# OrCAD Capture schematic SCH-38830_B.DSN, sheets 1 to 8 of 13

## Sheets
1 08 SPDIF: size C; title: MIMXRT1015-EVK; rev: B; company: Freescale Semiconductor; note: SCH-38830, PDF: SPF-38830; note: 6501 William Cannon Drive West; note: Austin, TX 78735-8598
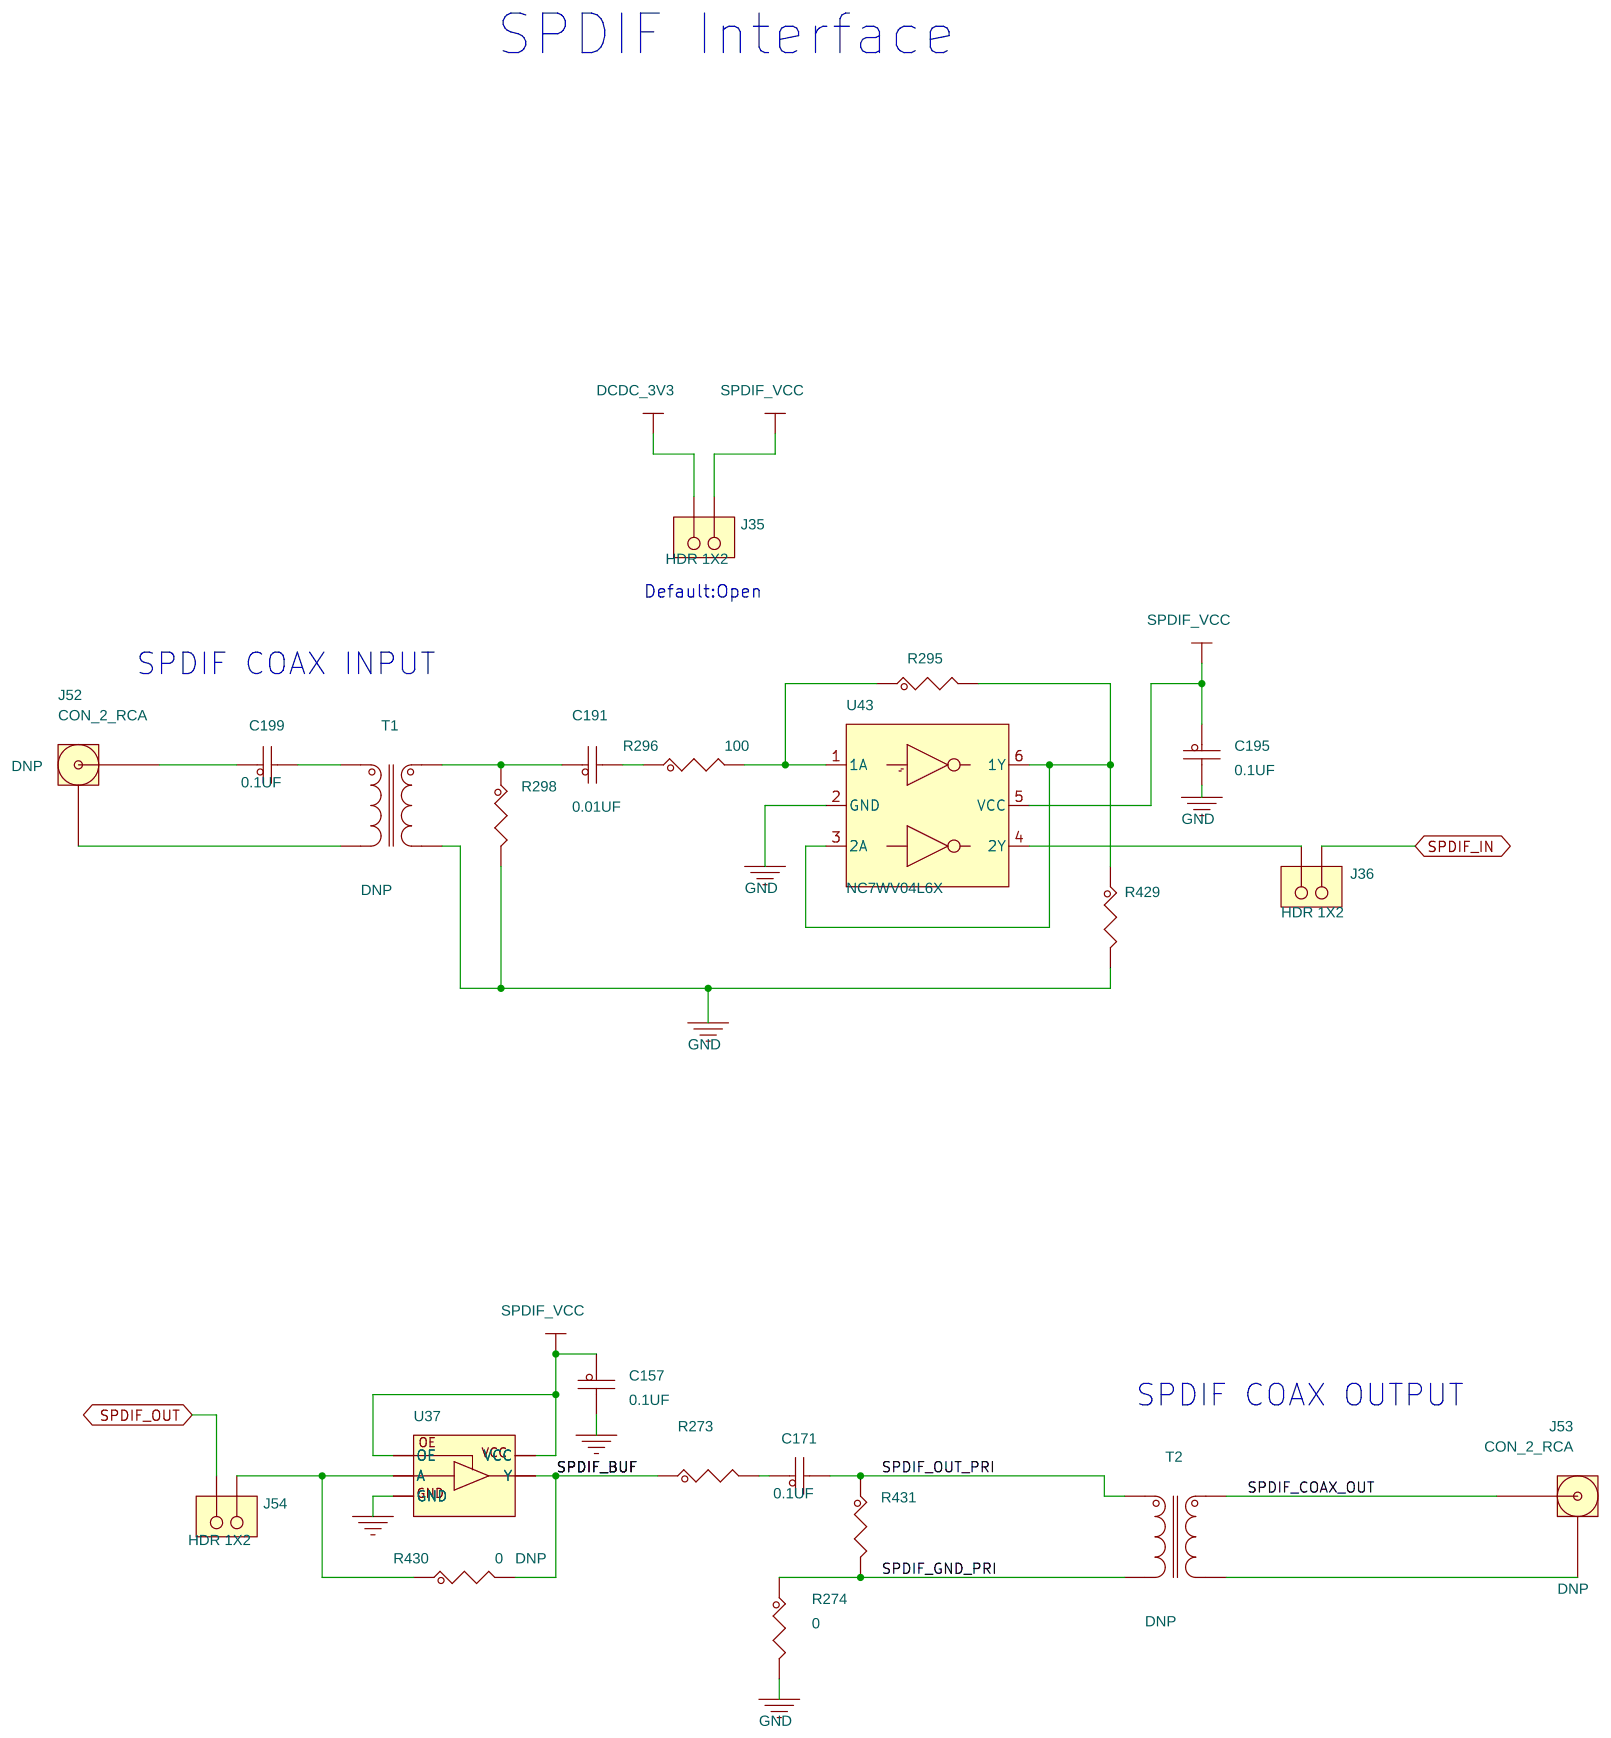
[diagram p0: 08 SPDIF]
2 01 COVER: company: NXP Semiconductors
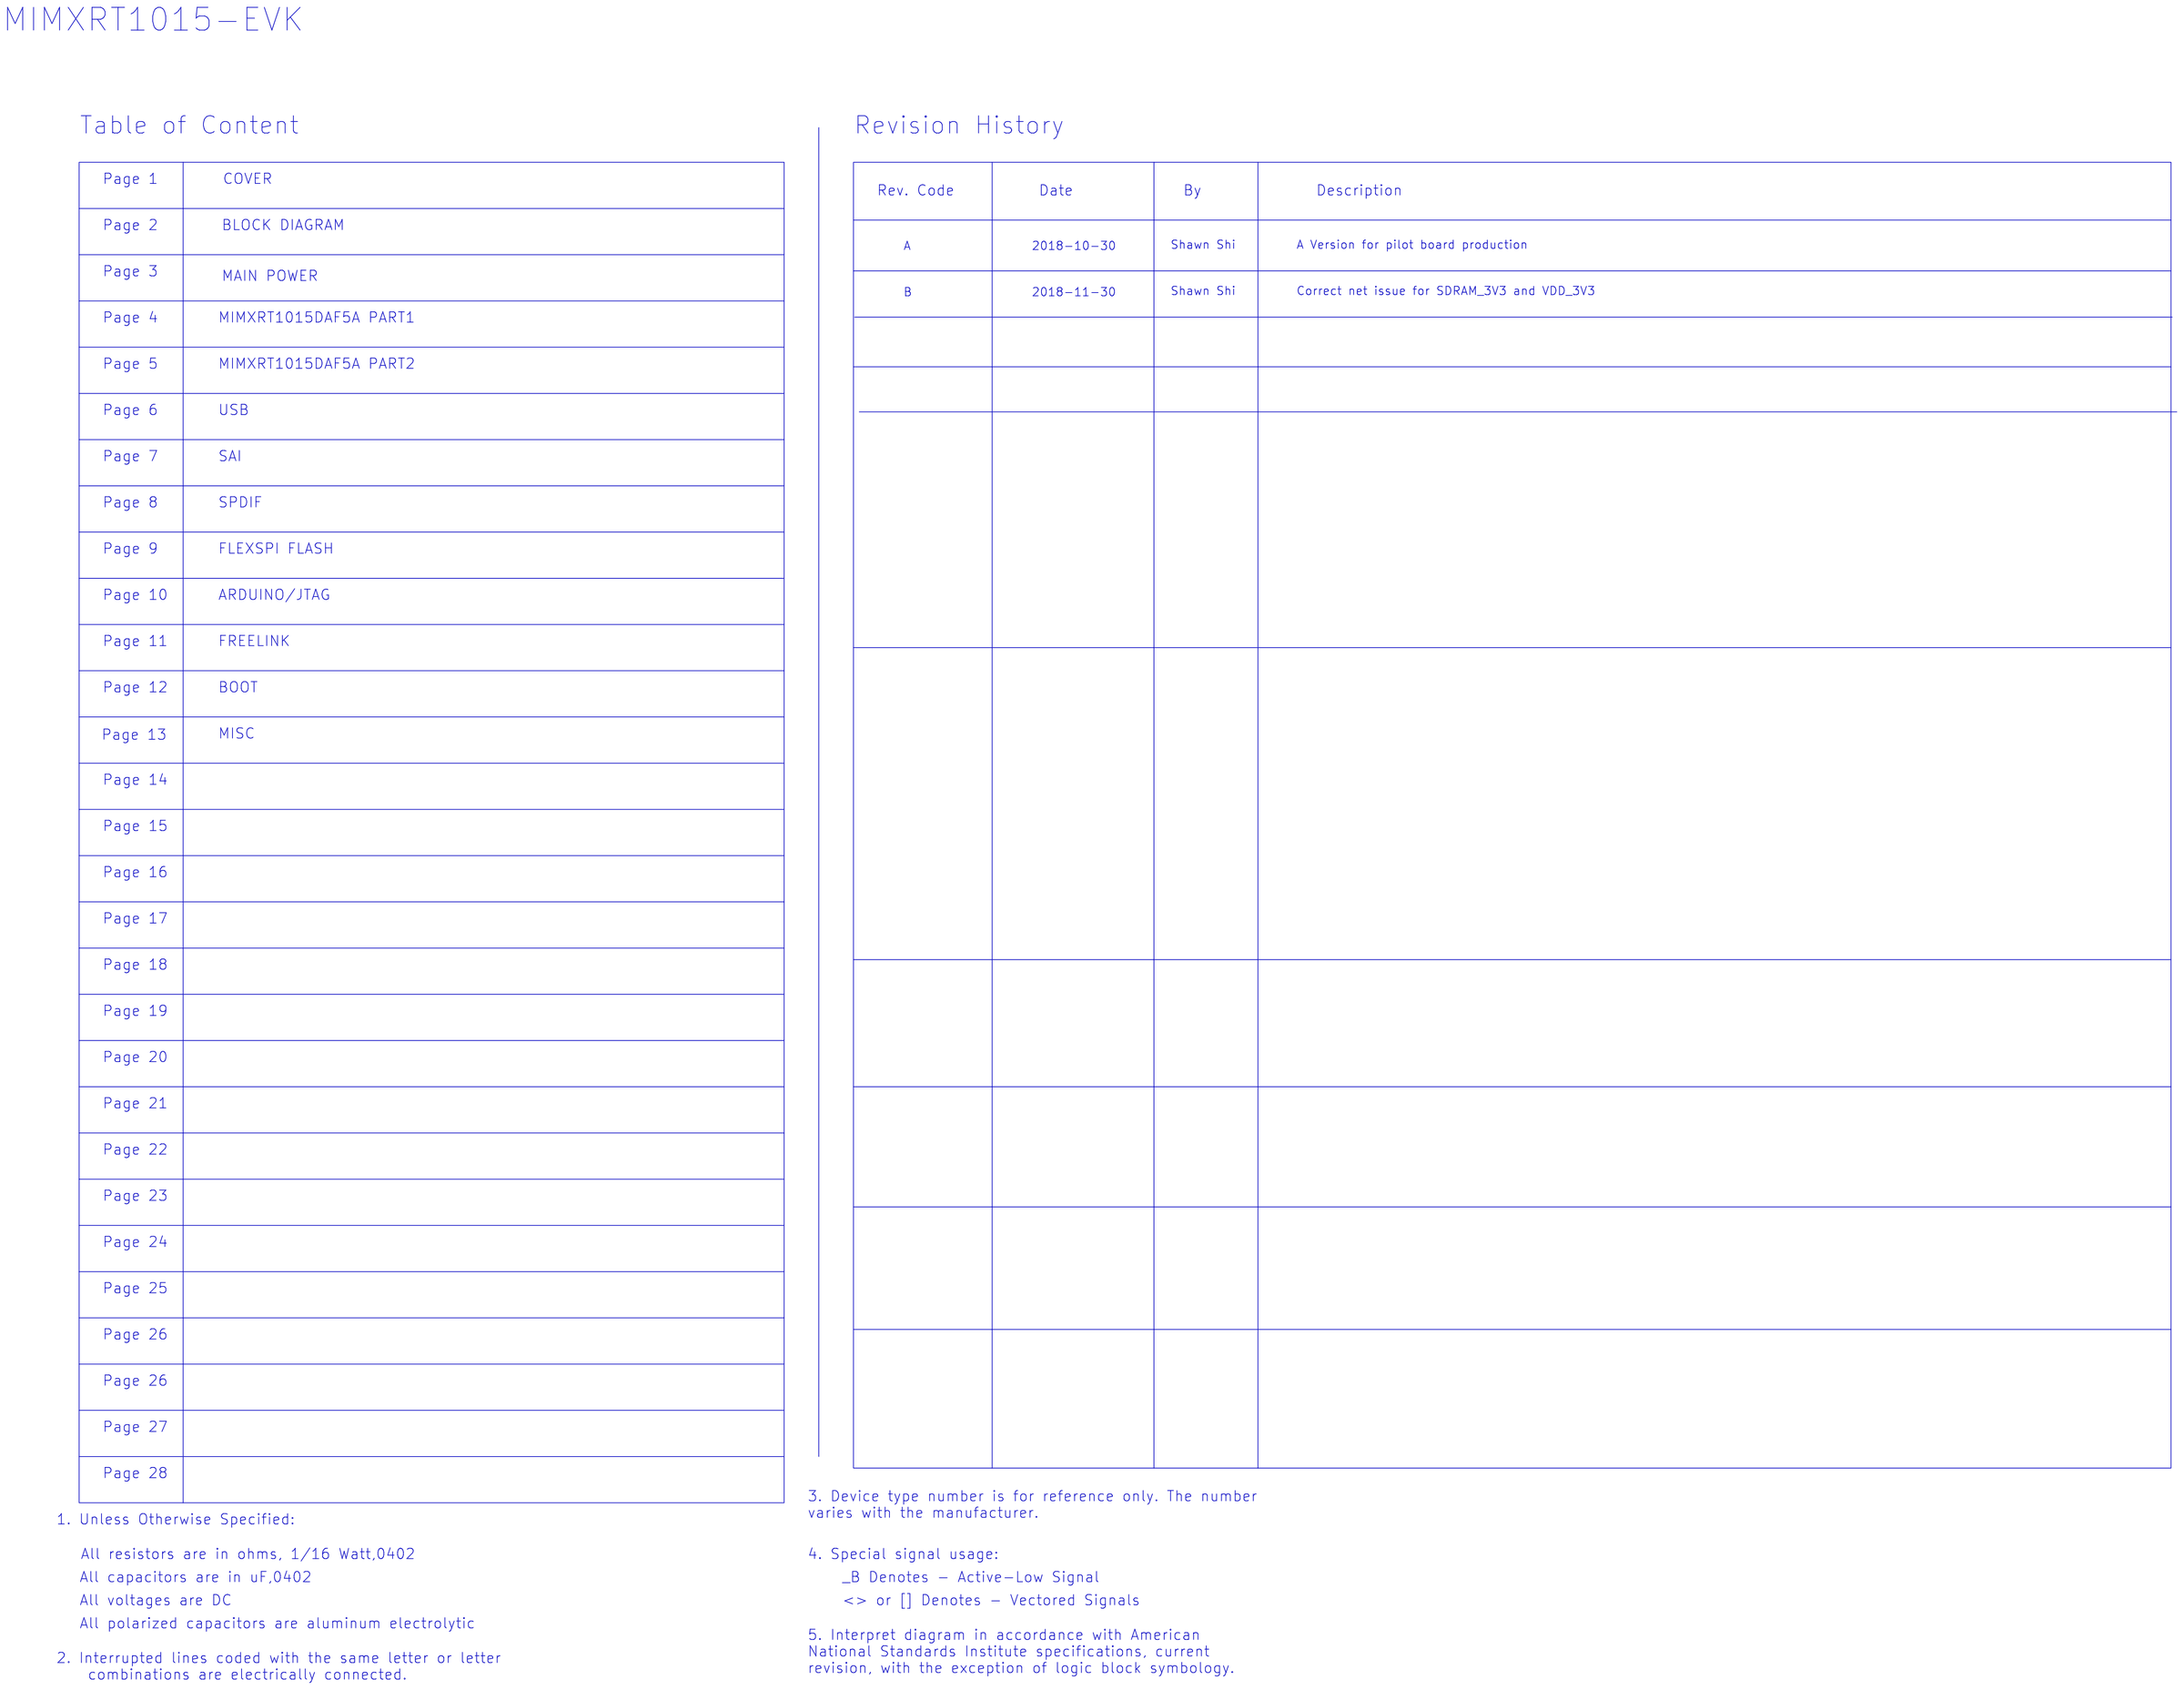
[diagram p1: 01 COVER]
3 02 BLOCK DIAGRAM
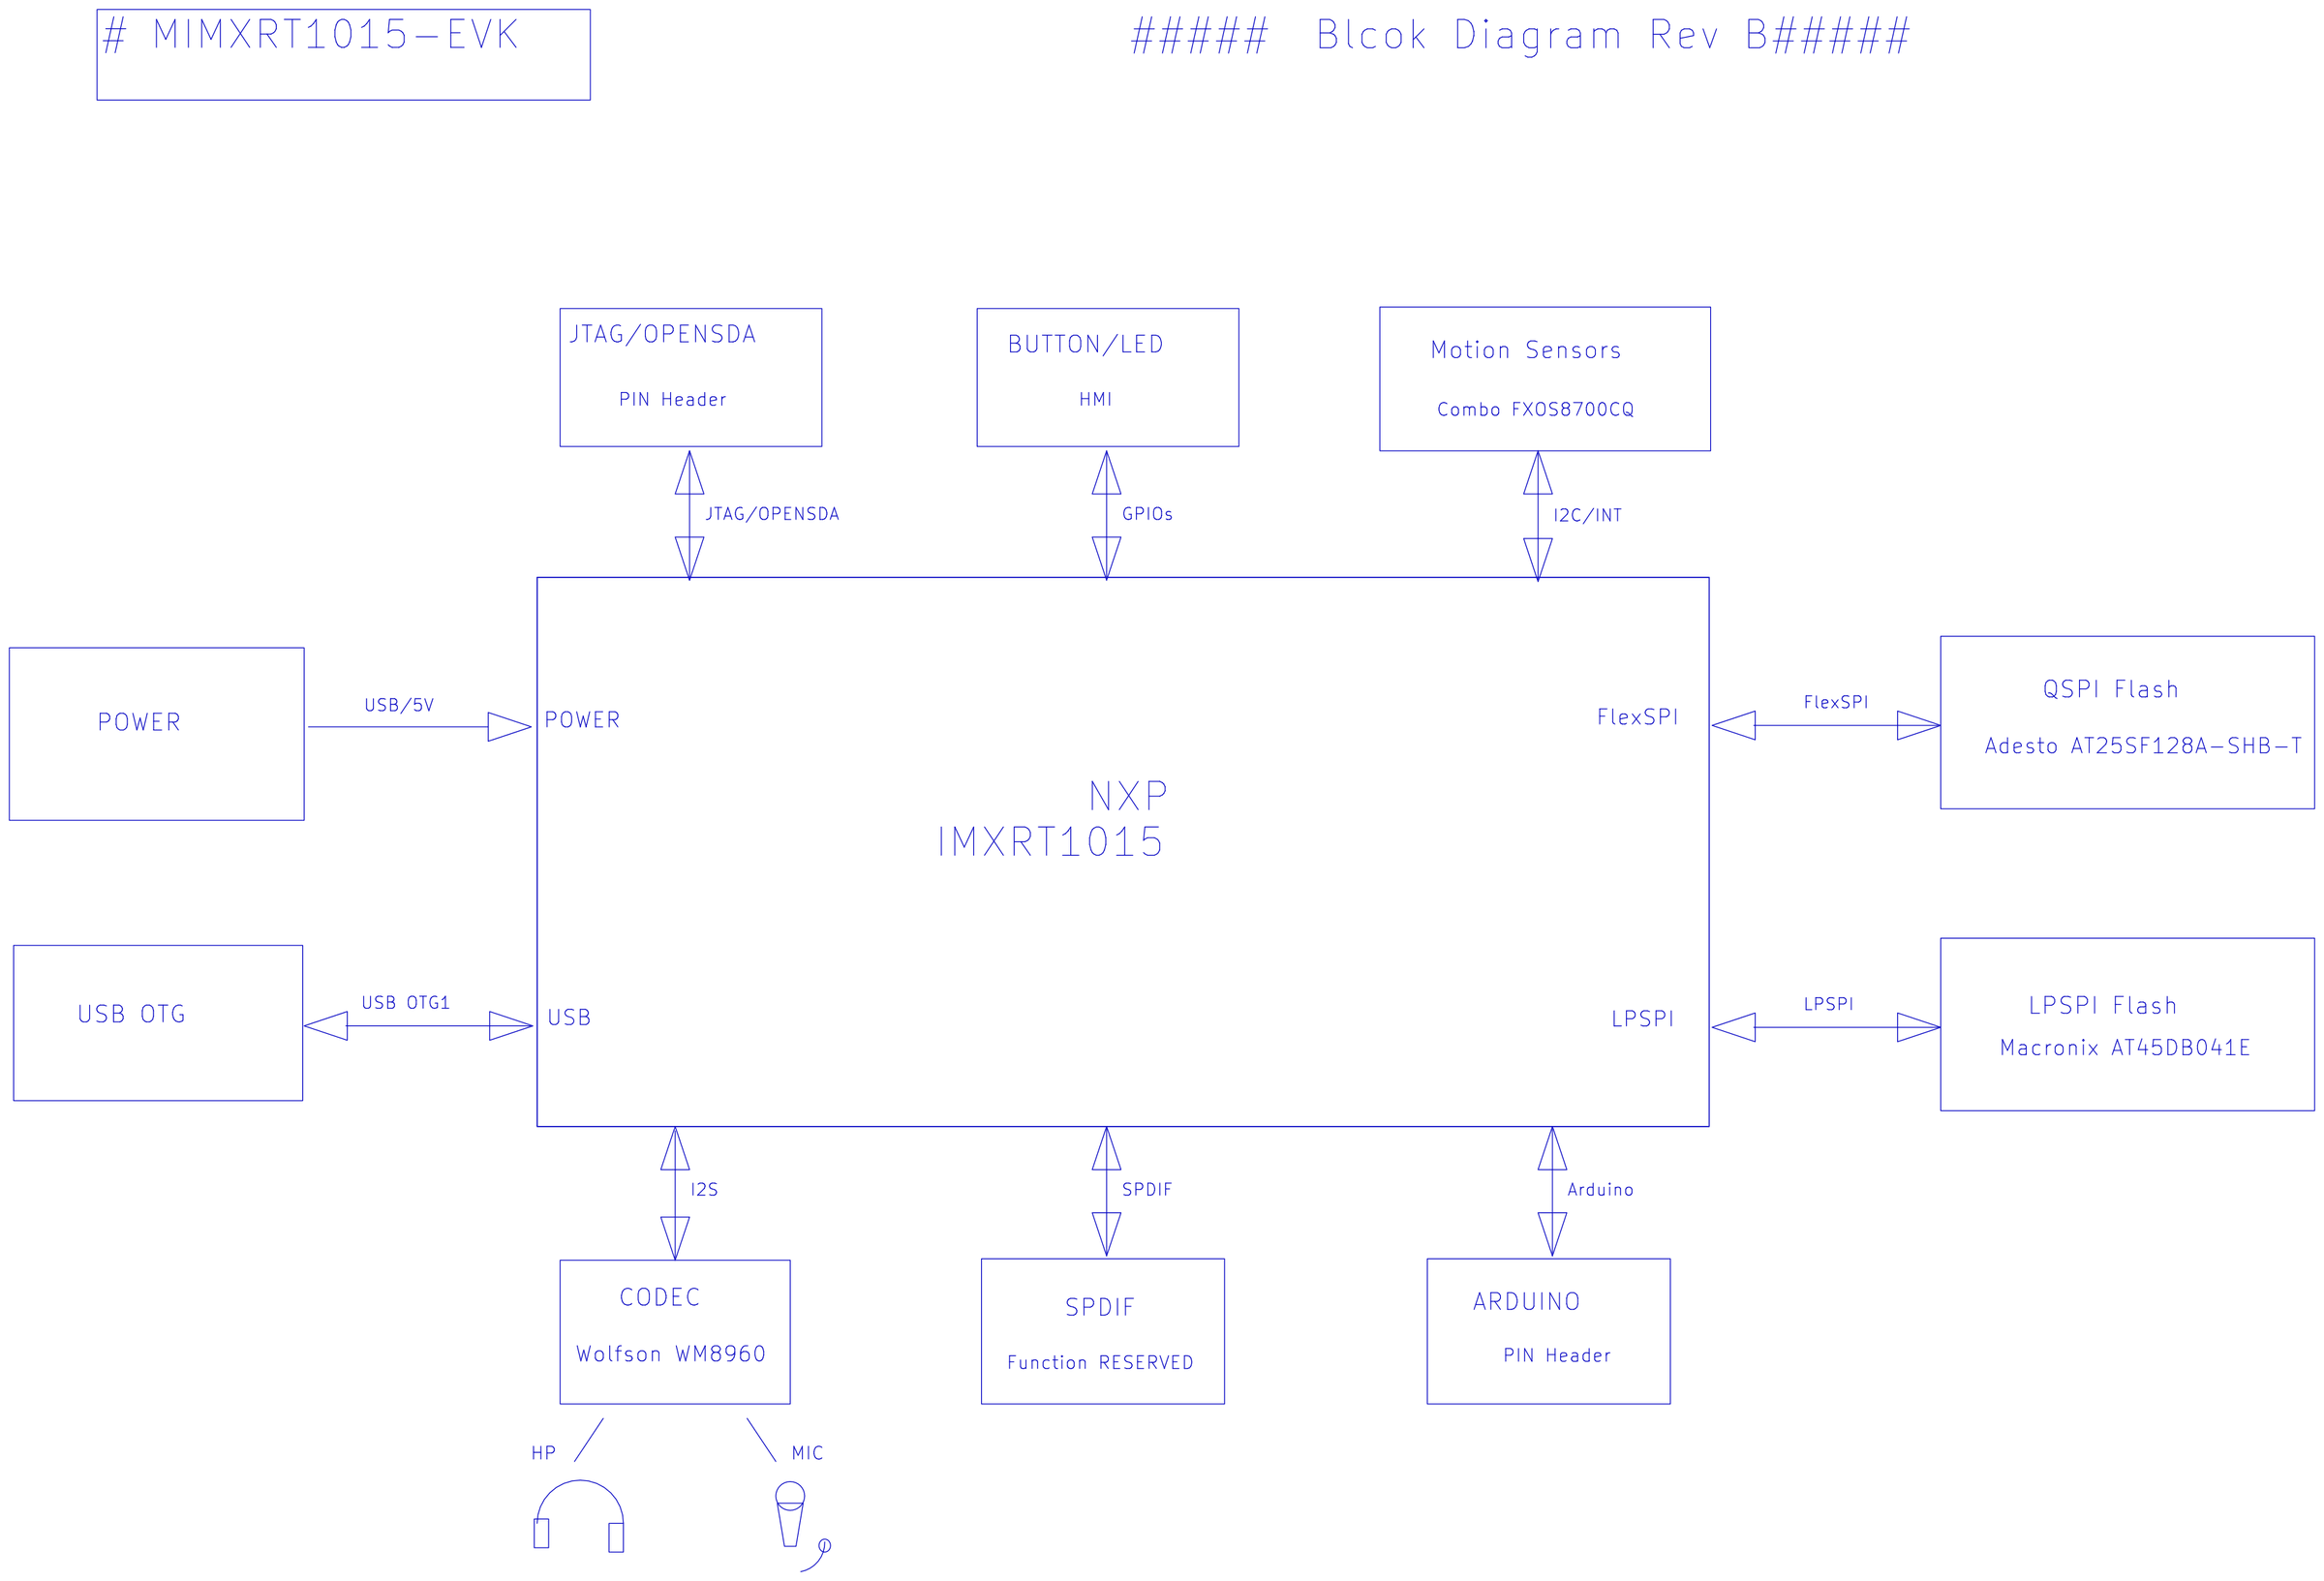
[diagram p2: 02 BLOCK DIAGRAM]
4 03 MAIN POWER: size C
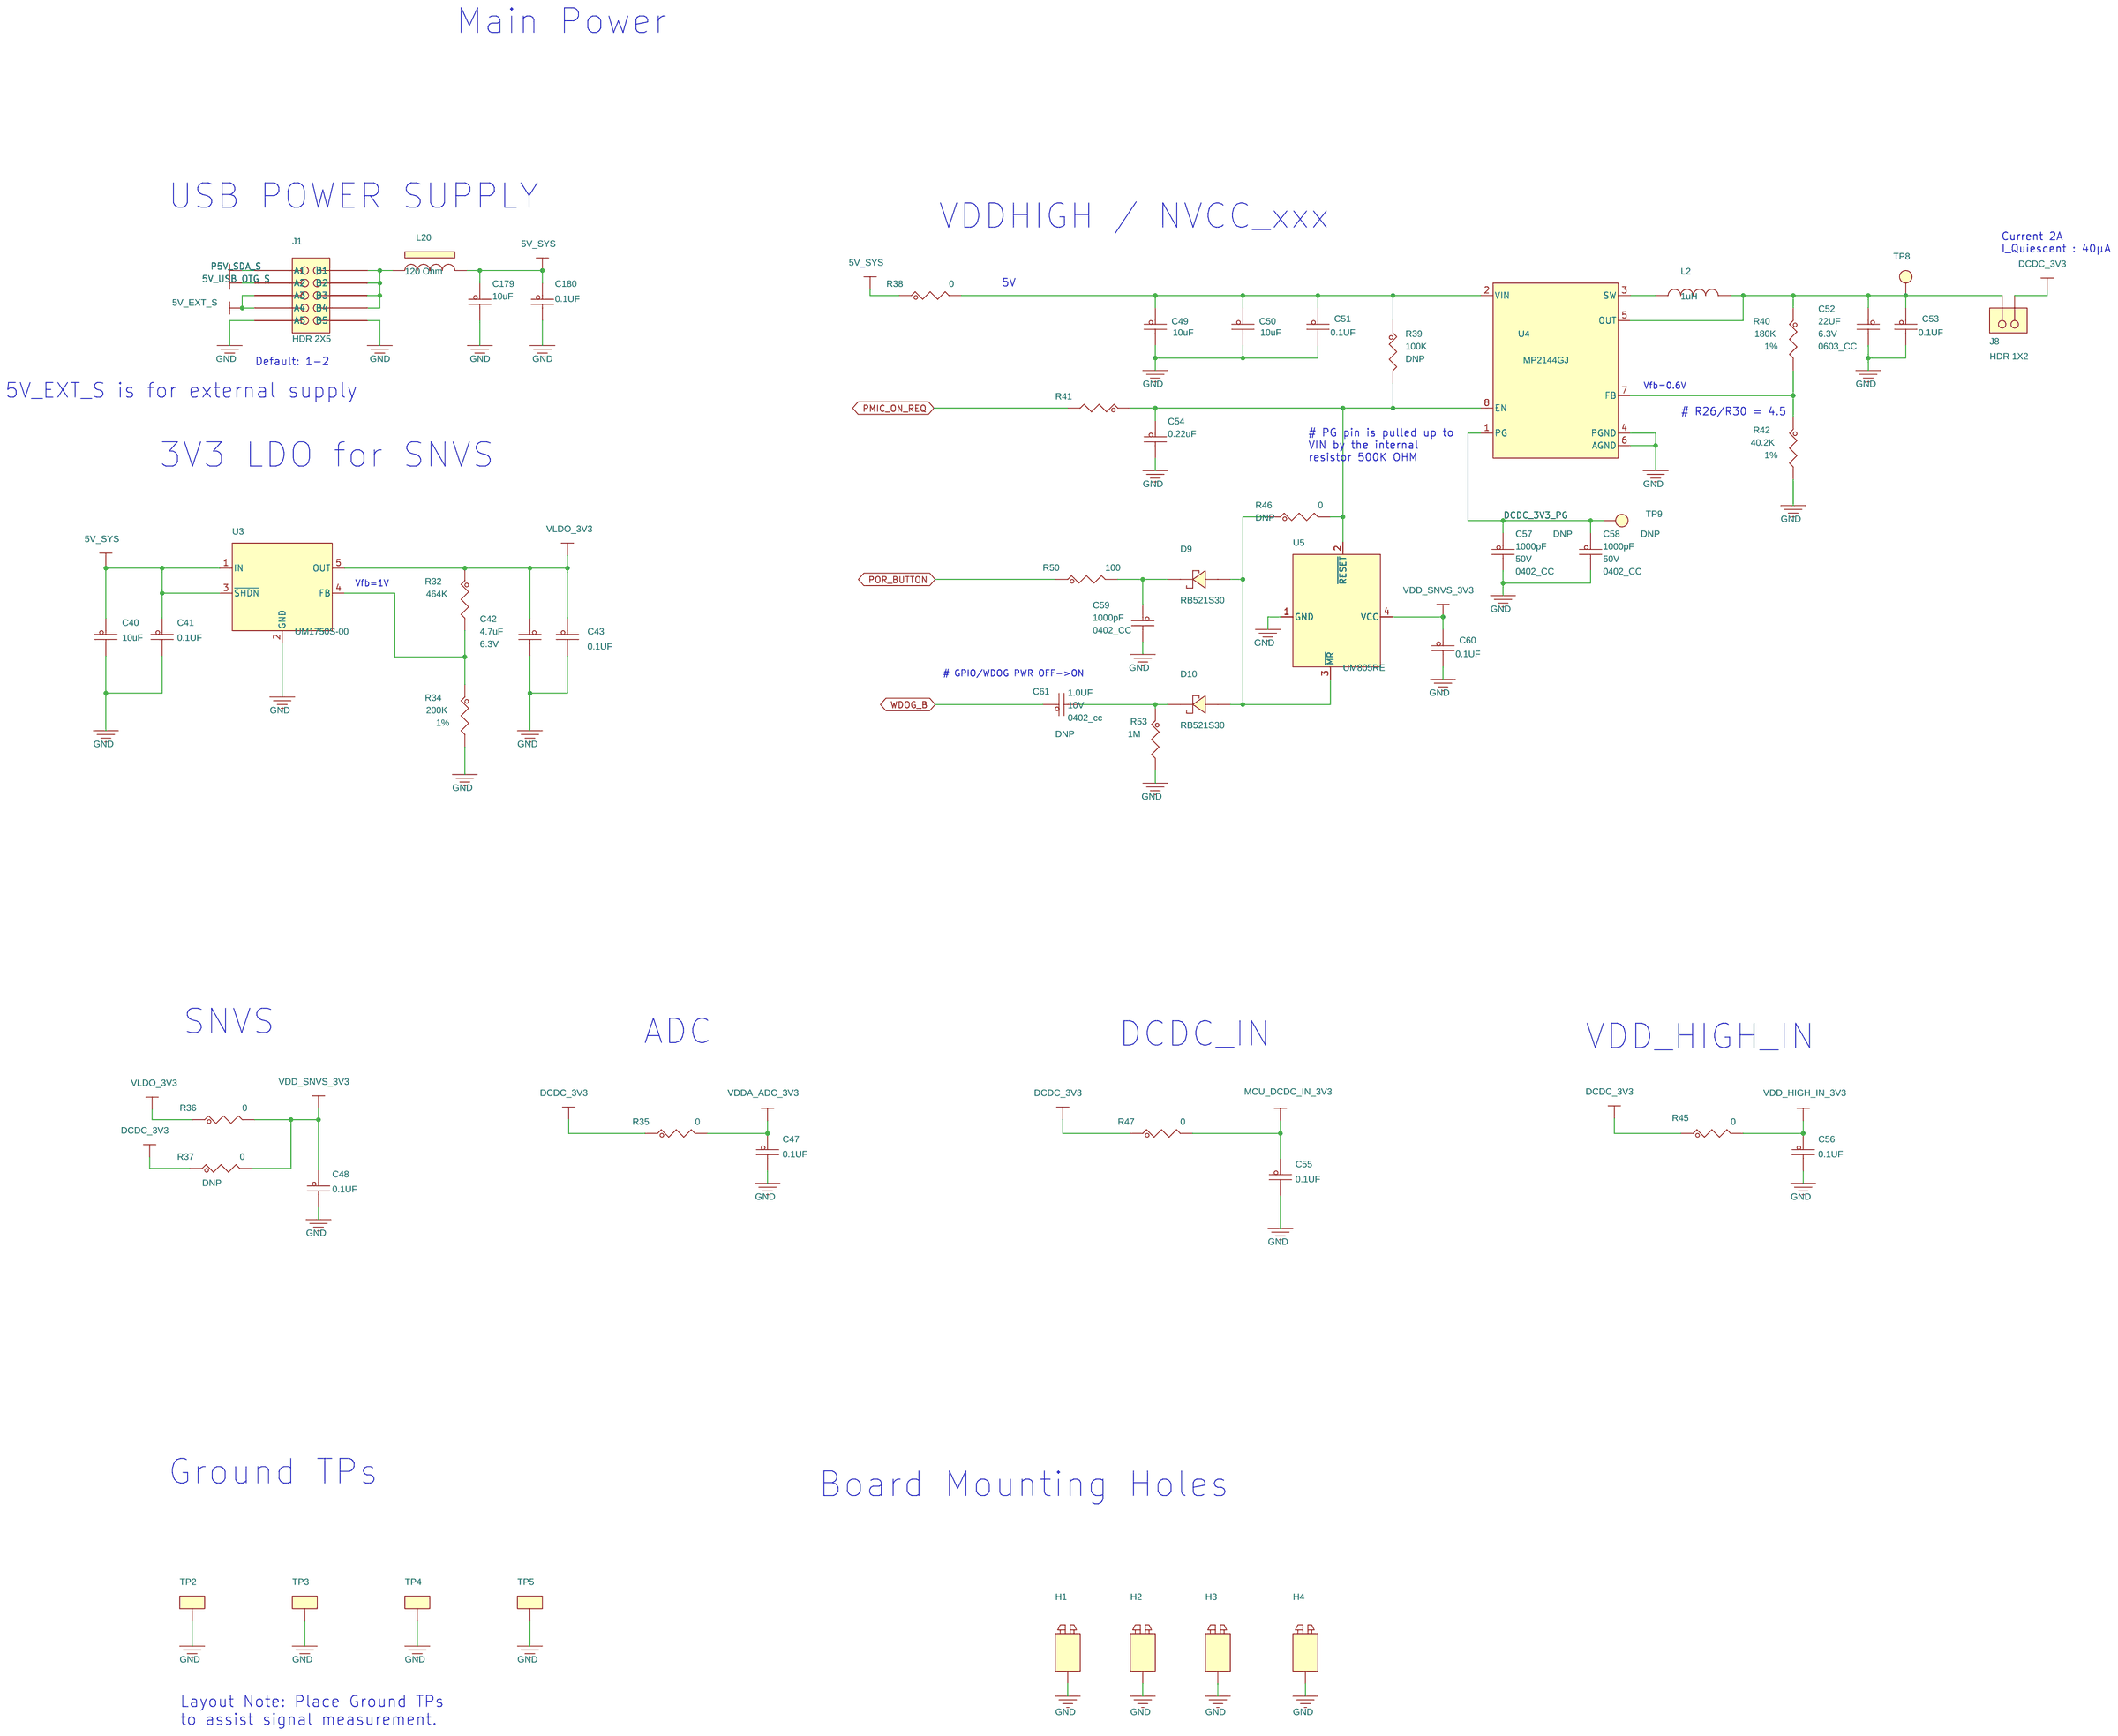
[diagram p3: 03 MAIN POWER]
5 04 MIMXRT1015DAF5A PART1: size C
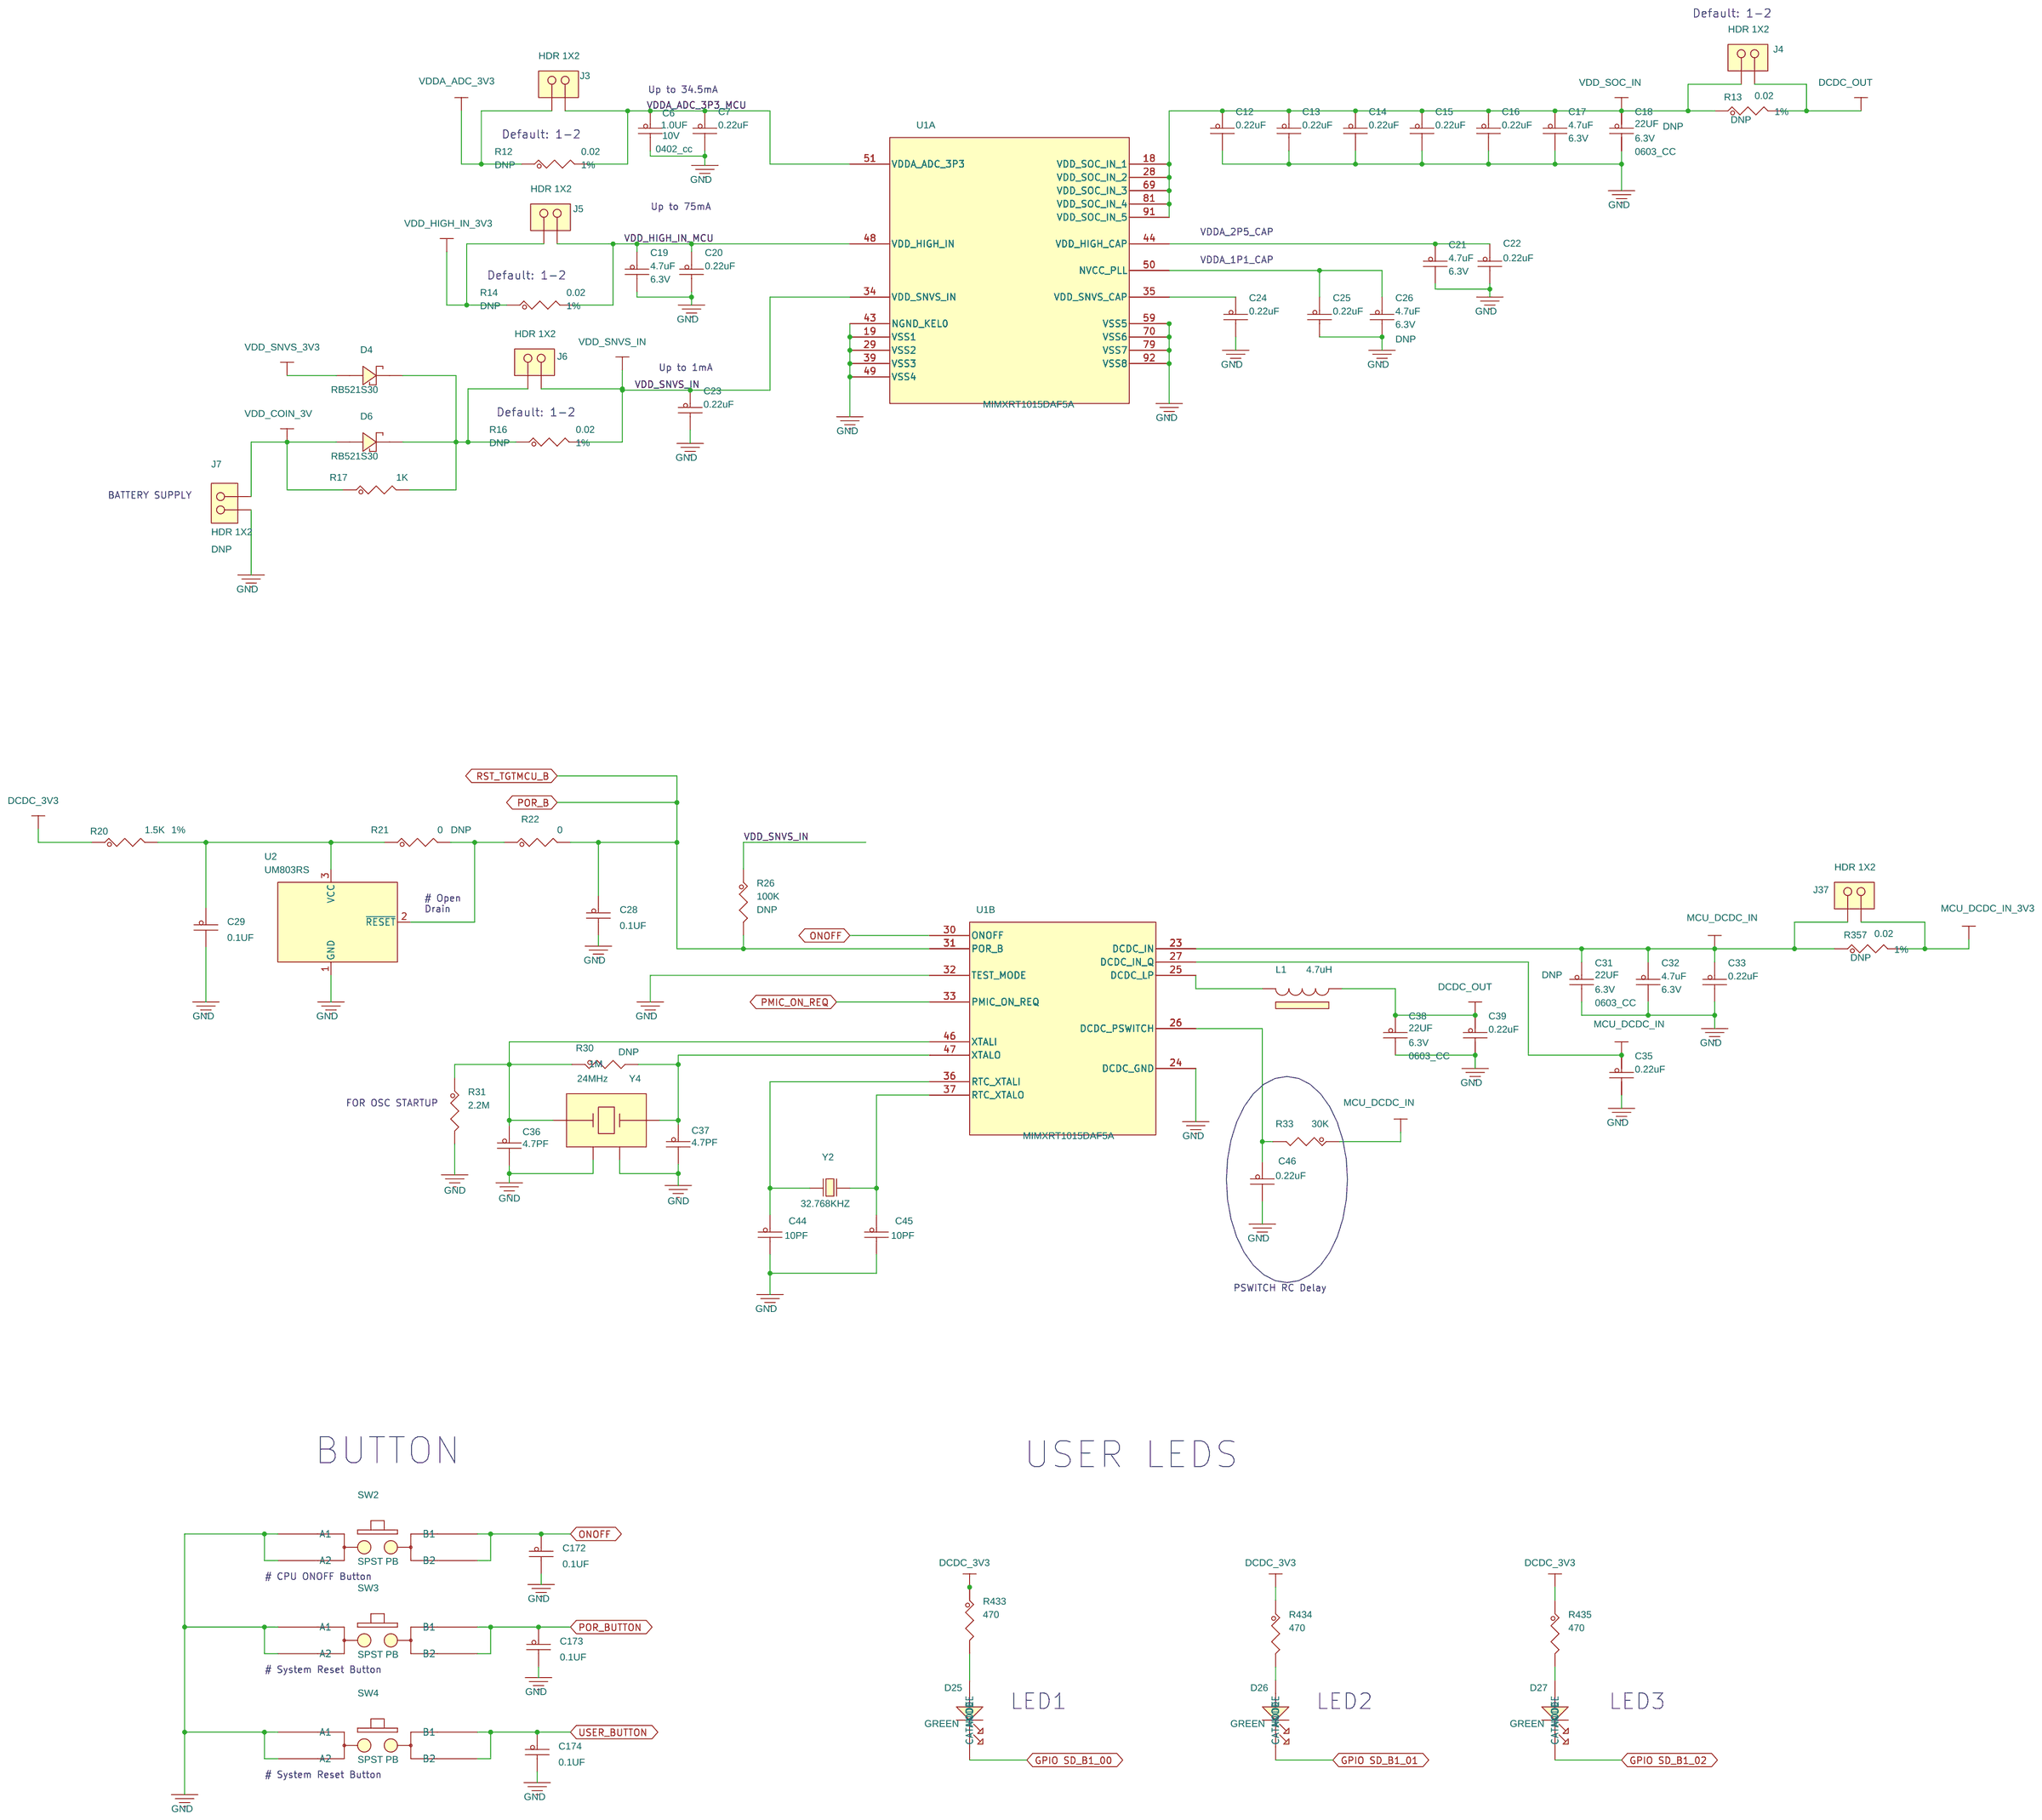
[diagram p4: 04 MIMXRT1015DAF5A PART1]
6 05 MIMXRT1015DAF5A PART2: size C
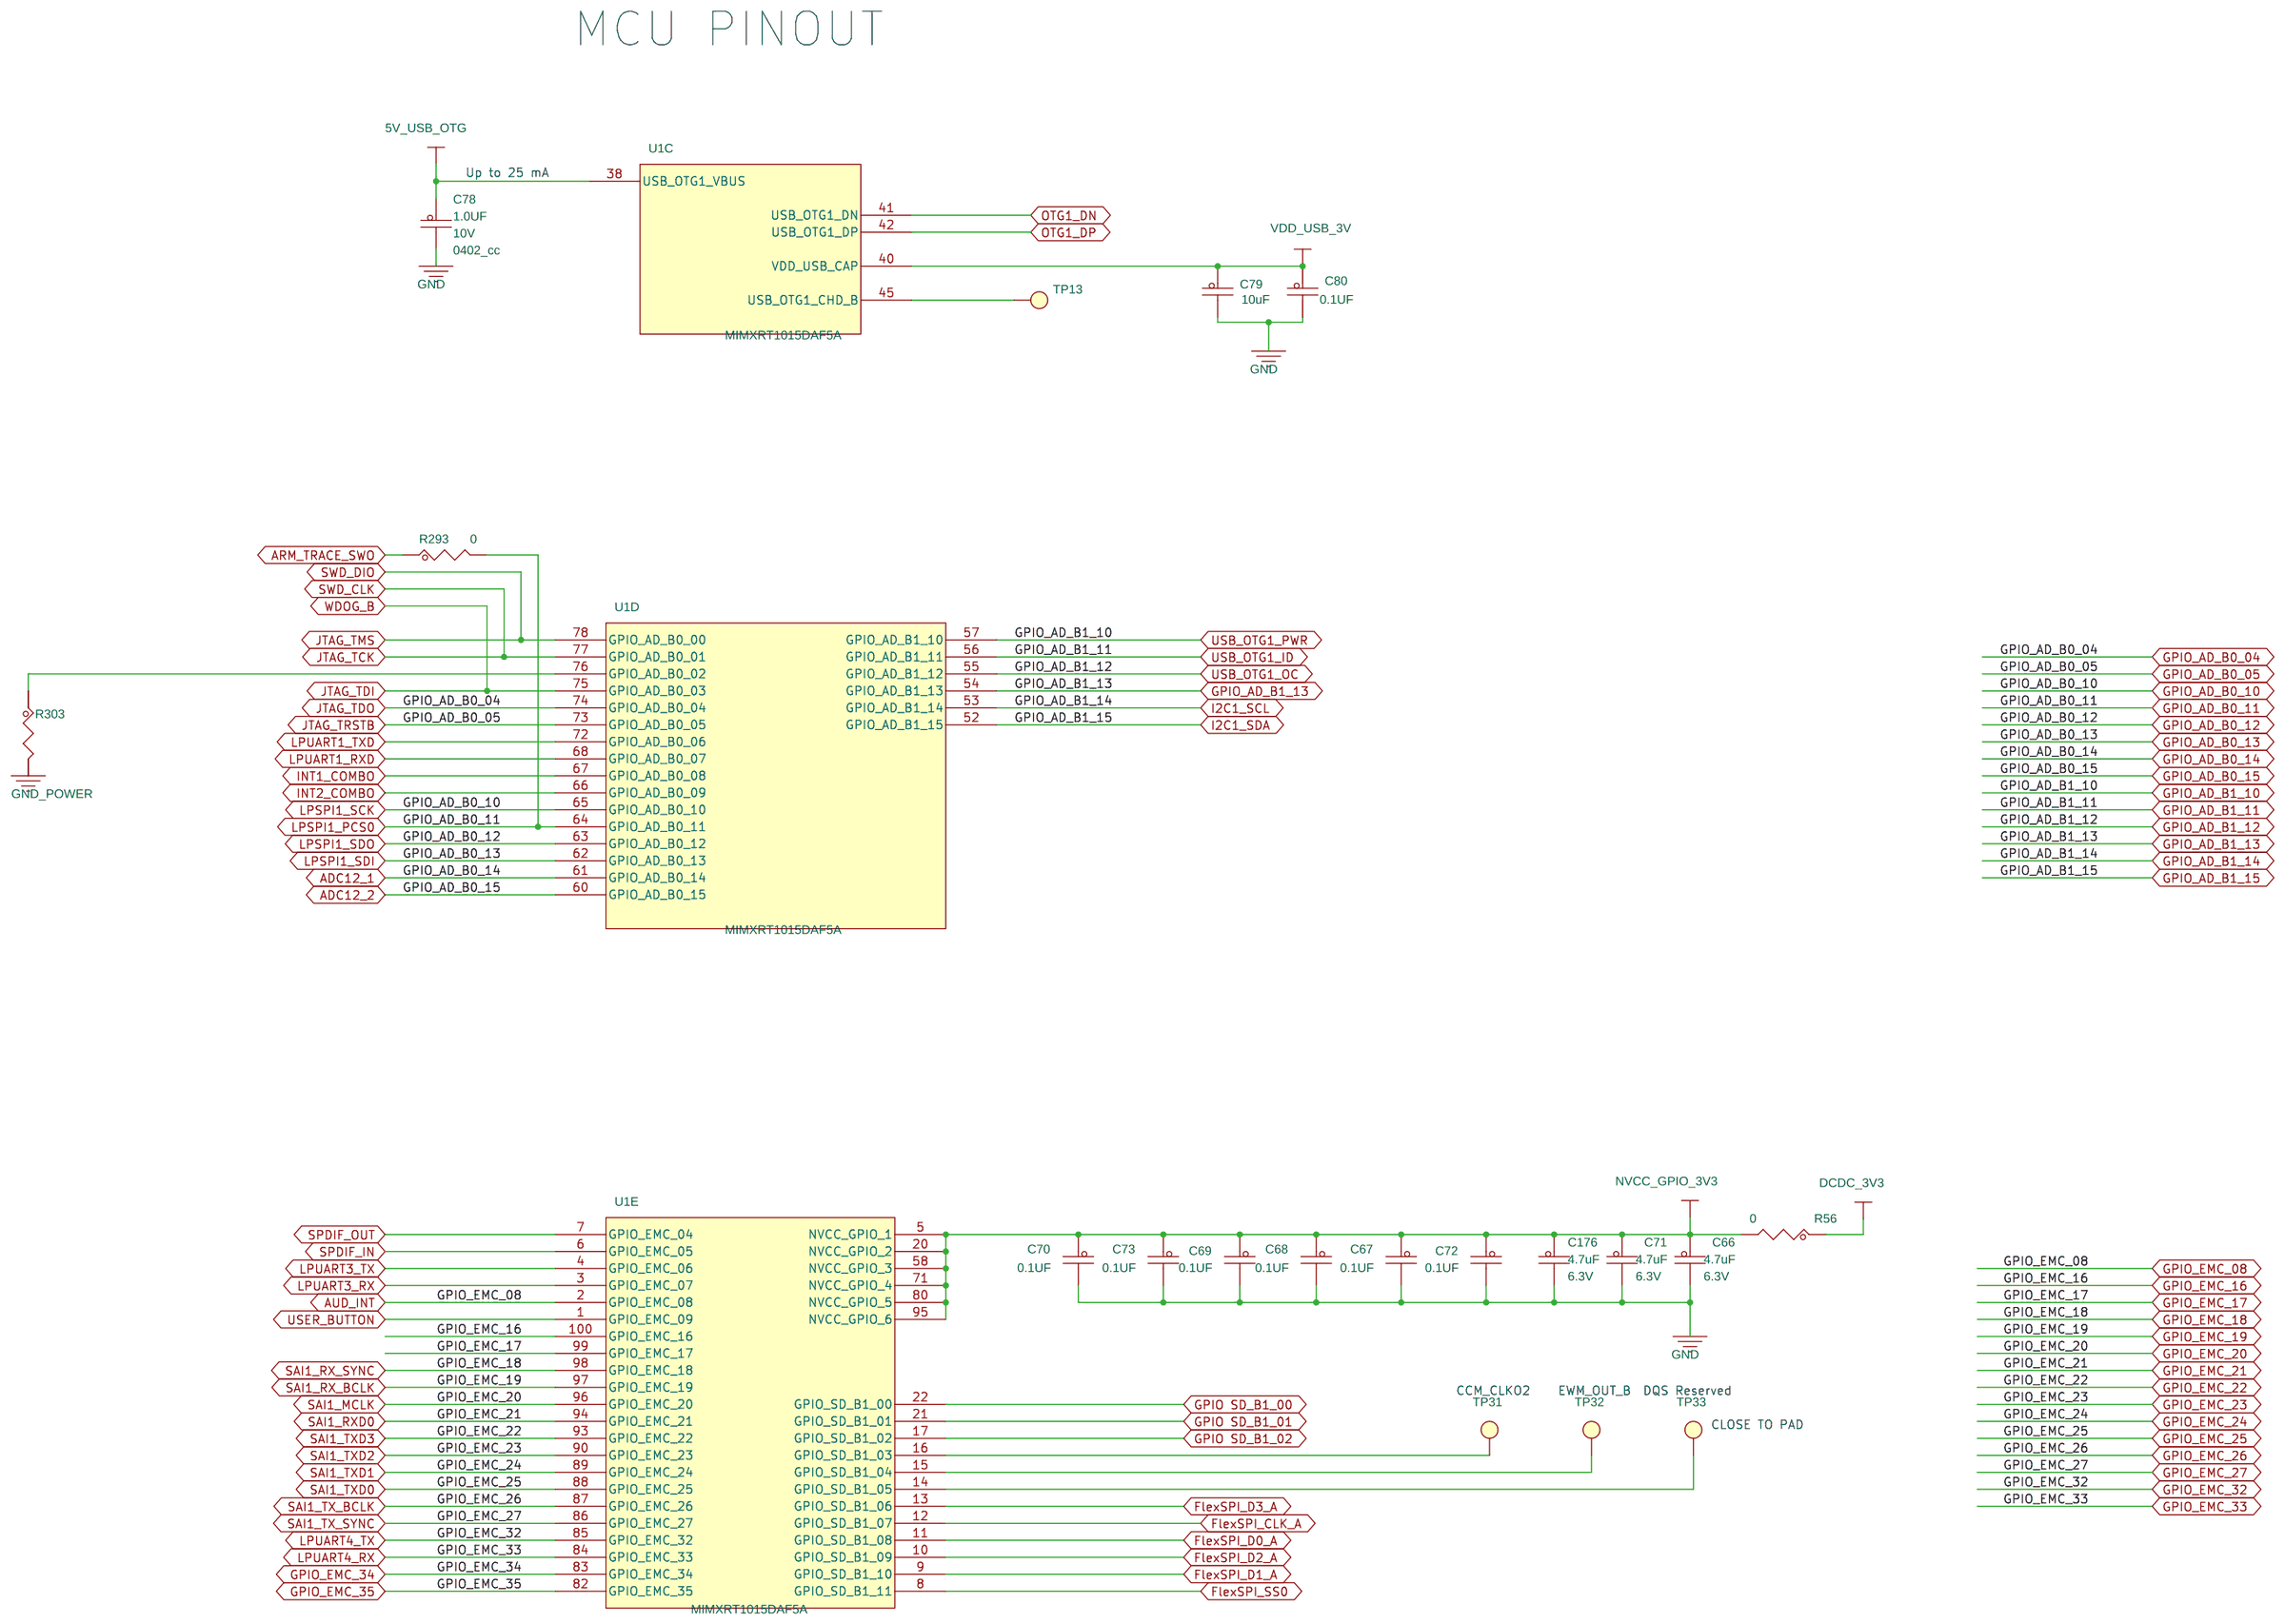
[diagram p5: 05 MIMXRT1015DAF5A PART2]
7 06 USB: size C
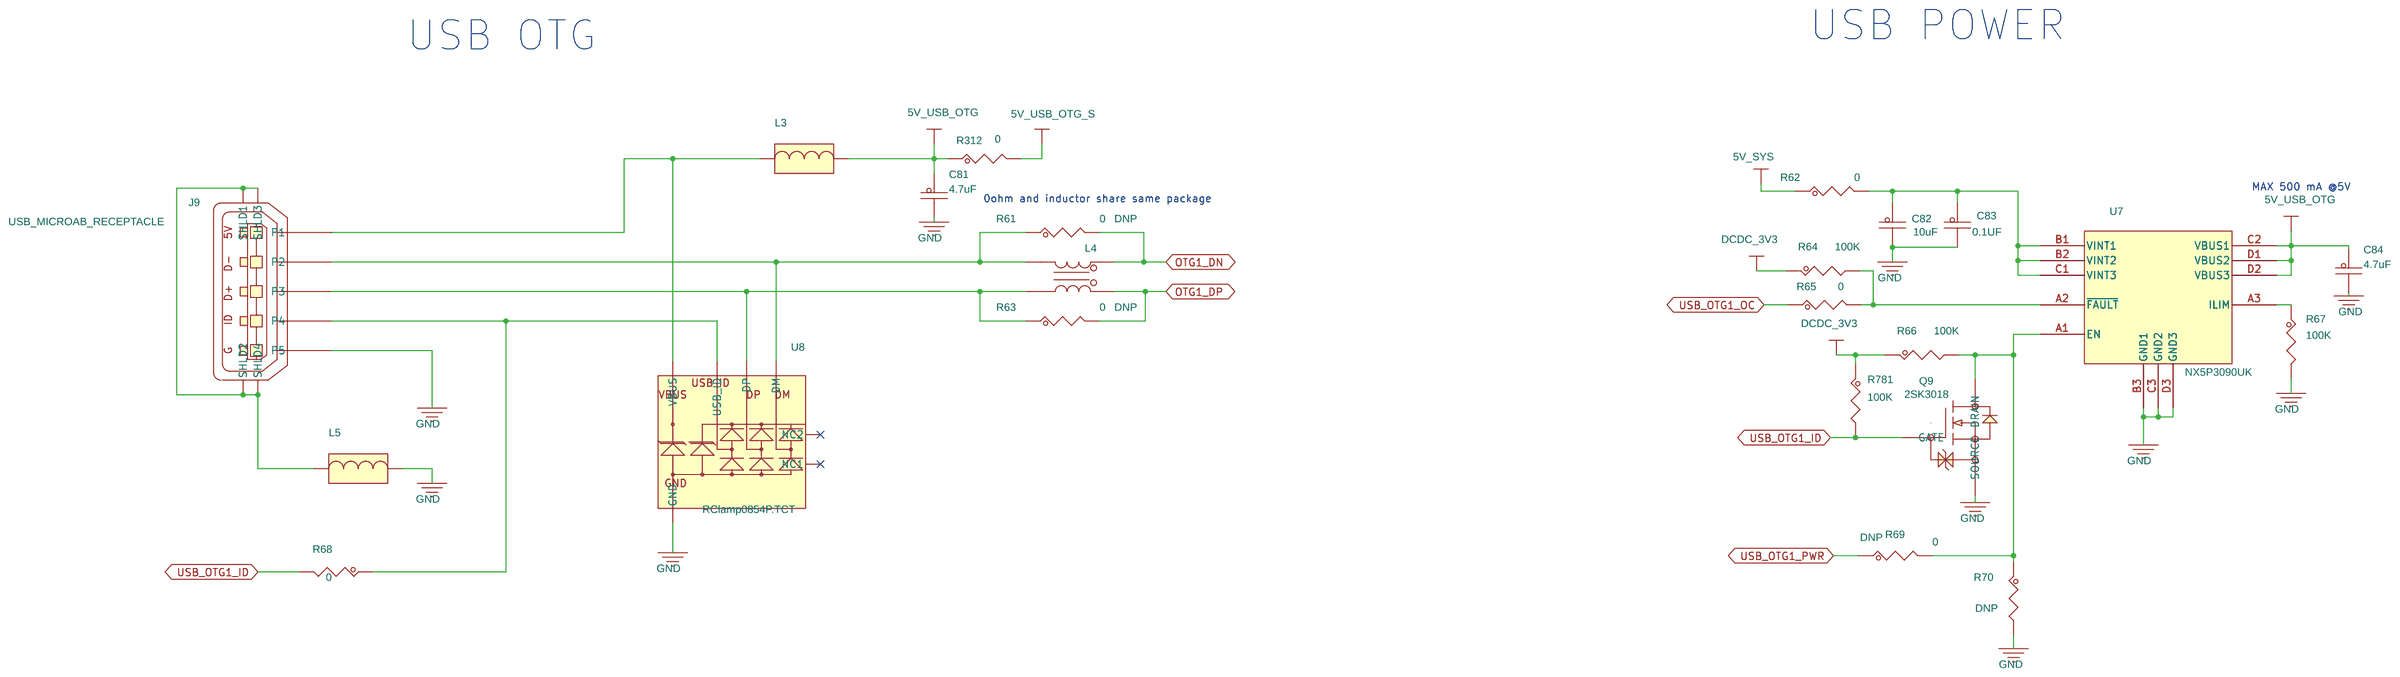
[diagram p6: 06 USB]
8 07 SAI: size C
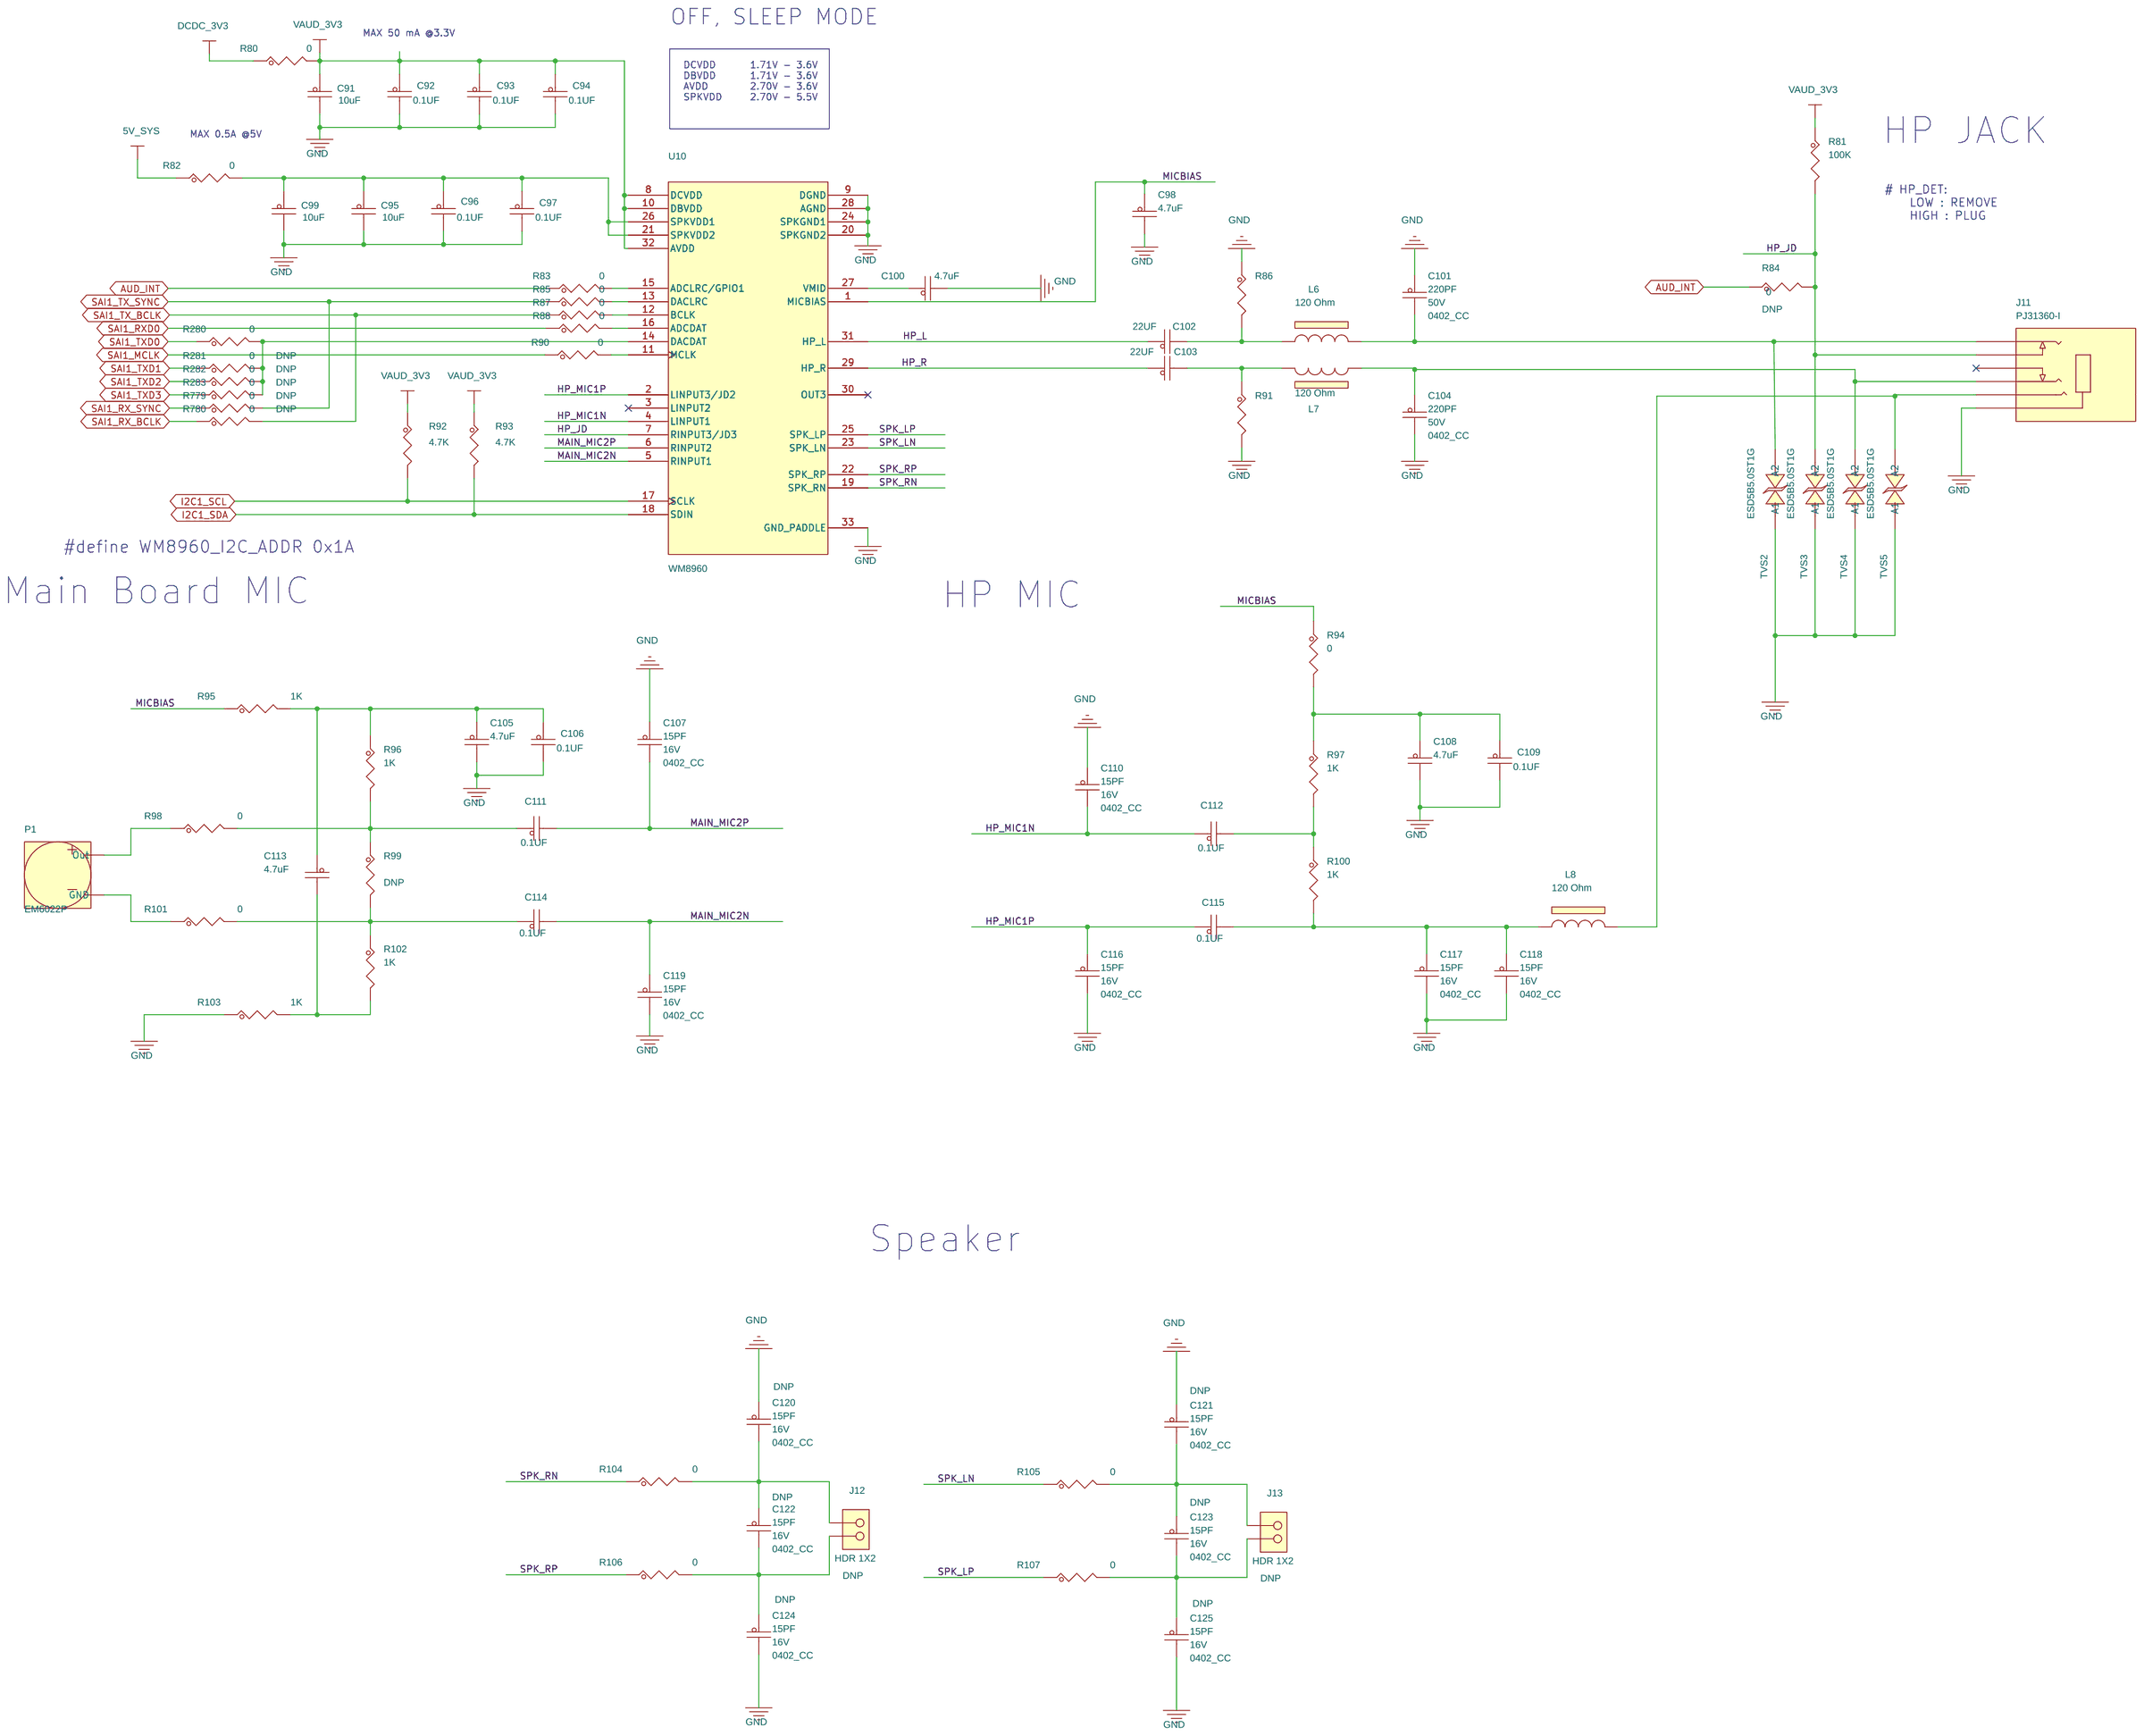
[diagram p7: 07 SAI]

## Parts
sheet 03 MAIN POWER
C40  10uF  [CC0603_OV]
C41  0.1UF  [CC0402_25]
C42  4.7uF  [0402_CC]
C43  0.1UF  [CC0402_25]
C47  0.1UF  [CC0402_25]
C48  0.1UF  [CC0402_25]
C49  10uF  [CC0603_OV]
C50  10uF  [CC0603_OV]
C51  0.1UF  [CC0402_25]
C52  22UF  [0603_CC]
C53  0.1UF  [CC0402_25]
C54  0.22uF  [0402_CC]
C55  0.1UF  [CC0402_25]
C56  0.1UF  [CC0402_25]
C57  1000pF  [0402_CC]
C58  1000pF  [0402_CC]
C59  1000pF  [0402_CC]
C60  0.1UF  [CC0402_25]
C61  1.0UF  [0402_cc]
C179  10uF  [CC0603_OV]
C180  0.1UF  [CC0402_25]
D9  RB521S30  [SOD523]
D10  RB521S30  [SOD523]
H1  .635" LONG  [spacer_139t]
H2  .635" LONG  [spacer_139t]
H3  .635" LONG  [spacer_139t]
H4  .635" LONG  [spacer_139t]
J1  HDR 2X5  [hdr205]
J8  HDR 1X2  [HDR102]
L2  1uH  [ind_4020]
L20  120 Ohm  [0402_CC]
R32  464K  [0402_CC]
R34  200K  [0402_CC]
R35  0  [0402_CC]
R36  0  [0402_CC]
R37  0  [0402_CC]
R38  0  [0402_CC]
R39  100K  [0402_CC]
R40  180K  [0402_CC]
R41  10K  [0402_CC]
R42  40.2K  [0402_CC]
R45  0  [0402_CC]
R46  0  [0402_CC]
R47  0  [0402_CC]
R50  100  [0402_CC]
R53  1M  [0402_CC]
TP2  5006  [tp_th_063]
TP3  5006  [tp_th_063]
TP4  5006  [tp_th_063]
TP5  5006  [tp_th_063]
TP8  TP_35MIL  [testpoint_35mil]
TP9  TP_35MIL  [testpoint_35mil]
U3  UM1750S-00  [sot23-5_a]
U4  MP2144GJ  [tsot23_8_0p65_2x1]
U5  UM805RE  [sot_143]
sheet 04 MIMXRT1015DAF5A PART1
C6  1.0UF  [0402_cc]
C7  0.22uF  [0402_CC]
C12  0.22uF  [0402_CC]
C13  0.22uF  [0402_CC]
C14  0.22uF  [0402_CC]
C15  0.22uF  [0402_CC]
C16  0.22uF  [0402_CC]
C17  4.7uF  [0402_CC]
C18  22UF  [0603_CC]
C19  4.7uF  [0402_CC]
C20  0.22uF  [0402_CC]
C21  4.7uF  [0402_CC]
C22  0.22uF  [0402_CC]
C23  0.22uF  [0402_CC]
C24  0.22uF  [0402_CC]
C25  0.22uF  [0402_CC]
C26  4.7uF  [0402_CC]
C28  0.1UF  [CC0402_25]
C29  0.1UF  [CC0402_25]
C31  22UF  [0603_CC]
C32  4.7uF  [0402_CC]
C33  0.22uF  [0402_CC]
C35  0.22uF  [0402_CC]
C36  4.7PF  [0402_CC]
C37  4.7PF  [0402_CC]
C38  22UF  [0603_CC]
C39  0.22uF  [0402_CC]
C44  10PF  [0402_CC]
C45  10PF  [0402_CC]
C46  0.22uF  [0402_CC]
C172  0.1UF  [CC0402_25]
C173  0.1UF  [CC0402_25]
C174  0.1UF  [CC0402_25]
D4  RB521S30  [SOD523]
D6  RB521S30  [SOD523]
D25  GREEN  [LED_0603]
D26  GREEN  [LED_0603]
D27  GREEN  [LED_0603]
J3  HDR 1X2  [HDR102]
J4  HDR 1X2  [HDR102]
J5  HDR 1X2  [HDR102]
J6  HDR 1X2  [HDR102]
J7  HDR 1X2  [HDR102]
J37  HDR 1X2  [HDR102]
L1  4.7uH  [ind_vls4012e]
R12  0.02  [RC0603_OV]
R13  0.02  [RC0603_OV]
R14  0.02  [RC0603_OV]
R16  0.02  [RC0603_OV]
R17  1K  [0402_CC]
R20  1.5K  [0402_CC]
R21  0  [0402_CC]
R22  0  [0402_CC]
R26  100K  [0402_CC]
R30  1M  [0402_CC]
R31  2.2M  [RC0402_25]
R33  30K  [RC0402_25]
R357  0.02  [RC0603_OV]
R433  470  [RC0402_25]
R434  470  [RC0402_25]
R435  470  [RC0402_25]
SW2  SPST PB  [SW4_PB_ESW_SM_P177]
SW3  SPST PB  [SW4_PB_ESW_SM_P177]
SW4  SPST PB  [SW4_PB_ESW_SM_P177]
U2  UM803RS  [sot-23]
Y2  32.768KHZ  [XTAL2-3p2x1p5-SM]
Y4  24MHz  [xtl4_2p1x1p7mm_sm]
sheet 05 MIMXRT1015DAF5A PART2
C66  4.7uF  [0402_CC]
C67  0.1UF  [CC0402_25]
C68  0.1UF  [CC0402_25]
C69  0.1UF  [CC0402_25]
C70  0.1UF  [CC0402_25]
C71  4.7uF  [0402_CC]
C72  0.1UF  [CC0402_25]
C73  0.1UF  [CC0402_25]
C78  1.0UF  [0402_cc]
C79  10uF  [CC0603_OV]
C80  0.1UF  [CC0402_25]
C176  4.7uF  [0402_CC]
R56  0  [0402_CC]
R293  0  [0402_CC]
R303  10K  [0402_CC]
TP13  TP_35MIL  [testpoint_35mil]
TP31  TP_35MIL  [testpoint_35mil]
TP32  TP_35MIL  [testpoint_35mil]
TP33  TP_35MIL  [testpoint_35mil]
U1  MIMXRT1015DAF5A  [LQFP100_0P5_14X14]  (sections A,B,C,D,E)
sheet 06 USB
C81  4.7uF  [0402_CC]
C82  10uF  [CC0603_OV]
C83  0.1UF  [CC0402_25]
C84  4.7uF  [0402_CC]
J9  USB_MICROAB_RECEPTACLE  [con_usb5_microab_0p65_sm]
L3  330 OHM  [ind_1608]
L4  90OHM  [ind4_choke_0805]
L5  330 OHM  [ind_1608]
Q9  2SK3018  [SOT323_3]
R61  0  [0402_CC]
R62  0  [0402_CC]
R63  0  [0402_CC]
R64  100K  [0402_CC]
R65  0  [0402_CC]
R66  100K  [0402_CC]
R67  100K  [RC0402_25]
R68  0  [0402_CC]
R69  0  [0402_CC]
R70  10K  [0402_CC]
R312  0  [0402_CC]
R781  100K  [0402_CC]
U7  NX5P3090UK  [wlcsp12_0p4_1p38x1p68mm_smdp]
U8  RClamp0854P.TCT  [slp1616p6]
sheet 07 SAI
C91  10uF  [CC0603_OV]
C92  0.1UF  [CC0402_25]
C93  0.1UF  [CC0402_25]
C94  0.1UF  [CC0402_25]
C95  10uF  [CC0603_OV]
C96  0.1UF  [CC0402_25]
C97  0.1UF  [CC0402_25]
C98  4.7uF  [0402_CC]
C99  10uF  [CC0603_OV]
C100  4.7uF  [0402_CC]
C101  220PF  [0402_CC]
C102  22UF  [CC0603_OV]
C103  22UF  [CC0603_OV]
C104  220PF  [0402_CC]
C105  4.7uF  [0402_CC]
C106  0.1UF  [CC0402_25]
C107  15PF  [0402_CC]
C108  4.7uF  [0402_CC]
C109  0.1UF  [CC0402_25]
C110  15PF  [0402_CC]
C111  0.1UF  [CC0402_25]
C112  0.1UF  [CC0402_25]
C113  4.7uF  [0402_CC]
C114  0.1UF  [CC0402_25]
C115  0.1UF  [CC0402_25]
C116  15PF  [0402_CC]
C117  15PF  [0402_CC]
C118  15PF  [0402_CC]
C119  15PF  [0402_CC]
C120  15PF  [0402_CC]
C121  15PF  [0402_CC]
C122  15PF  [0402_CC]
C123  15PF  [0402_CC]
C124  15PF  [0402_CC]
C125  15PF  [0402_CC]
J11  PJ31360-I  [con6_audjack_ra_th]
J12  HDR 1X2  [HDR102]
J13  HDR 1X2  [HDR102]
L6  120 Ohm  [0402_CC]
L7  120 Ohm  [0402_CC]
L8  120 Ohm  [0402_CC]
P1  EM6022P  [mic_WM-63PR]
R80  0  [0402_CC]
R81  100K  [0402_CC]
R82  0  [0402_CC]
R83  0  [0402_CC]
R84  0  [0402_CC]
R85  0  [0402_CC]
R86  10K  [0402_CC]
R87  0  [0402_CC]
R88  0  [0402_CC]
R90  0  [0402_CC]
R91  10K  [0402_CC]
R92  4.7K  [RC0402_25]
R93  4.7K  [RC0402_25]
R94  0  [0402_CC]
R95  1K  [0402_CC]
R96  1K  [0402_CC]
R97  1K  [0402_CC]
R98  0  [0402_CC]
R99  10K  [0402_CC]
R100  1K  [0402_CC]
R101  0  [0402_CC]
R102  1K  [0402_CC]
R103  1K  [0402_CC]
R104  0  [0402_CC]
R105  0  [0402_CC]
R106  0  [0402_CC]
R107  0  [0402_CC]
R280  0  [0402_CC]
R281  0  [0402_CC]
R282  0  [0402_CC]
R283  0  [0402_CC]
R779  0  [0402_CC]
R780  0  [0402_CC]
TVS2  ESD5B5.0ST1G  [diode2_sod523]
TVS3  ESD5B5.0ST1G  [diode2_sod523]
TVS4  ESD5B5.0ST1G  [diode2_sod523]
TVS5  ESD5B5.0ST1G  [diode2_sod523]
U10  WM8960  [qfn32_s142ep]
sheet 08 SPDIF
C157  0.1UF  [0402_CC]
C171  0.1UF  [0402_CC]
C191  0.01UF  [0402_CC]
C195  0.1UF  [0402_CC]
C199  0.1UF  [0402_CC]
J35  HDR 1X2  [HDR102]
J36  HDR 1X2  [HDR102]
J52  CON_2_RCA  [con2_rca_ra_th]
J53  CON_2_RCA  [con2_rca_ra_th]
J54  HDR 1X2  [HDR102]
R273  374  [RC0805_OV]
R274  0  [0402_CC]
R295  10K  [0402_CC]
R296  100  [0402_CC]
R298  75.0  [RC0805_OV]
R429  10K  [0402_CC]
R430  0  [0402_CC]
R431  93.1  [RC0603_OV]
T1  TTWB1010L  [xfmr6_6p6x6p2]
T2  TTWB1010L  [xfmr6_6p6x6p2]
U37  NL17SZ126DF  [SC-70]
U43  NC7WV04L6X  [MICROPAK_6P]

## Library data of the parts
C40 C49 C50 C79 C82 C91 C95 C99 C179 = CAP_NP: CAP CER 10UF 10V 10% X5R 0603; AGILE_PN: 150-78675; CAD_APPROVED: Yes; FPLIST: CC0603_OV,CC0603,0603_CC; HEIGHT: 1.016MM; MFG_NAME01: MURATA; MFG_PN01: GRM188R61A106KE69D; ROHS: Yes; Temp_Range: -55°C ~ 85°C; Tolerance: 10%; VOLTAGE: 10v
C28 C29 C41 C43 C47 C48 C51 C53 C55 C56 C60 C67-C70 C72 C73 C80 C83 C92-C94 C96 C97 C106 C109 C111 C112 C114 C115 C157 C171-C174 C180 C195 C199 = CAP_NP: CAP CER 0.1UF 10V 10% X5R 0402; AGILE_PN: 150-75634; CAD_APPROVED: Yes; FPLIST: CC0402_25,CC0402_HD,0402_CC; HEIGHT: 0.64MM; MFG_NAME01: YAGEO AMERICA; MFG_PN01: CC0402KRX5R6BB104; ROHS: Yes; Tolerance: 10%; VOLTAGE: 10V
C17 C19 C21 C32 C42 C66 C71 C98 C100 C105 C108 C113 C176 = CAP_NP: CAP CER 4.7UF 6.3V 20% X5R 0402; AGILE_PN: 150-78463; CAD_APPROVED: Yes; FPLIST: CC0402_25,CC0402_HD,0402_CC; HEIGHT: 0.65MM; MFG_NAME01: TDK; MFG_PN01: C1005X5R0J475M050BC; ROHS: Yes; Tolerance: 20%; VOLTAGE: 6.3V; voltage rating: 6.3V
C38 C52 = CAP_NP: CAP CER 22UF 6.3V 20% X5R 0603; AGILE_PN: 150-78467; CAD_APPROVED: Yes; FPLIST: CC0603_OV,CC0603,0603_CC; HEIGHT: 1MM; MFG_NAME01: Samsung; MFG_PN01: CL10A226MQ8NRNE; ROHS: Yes; Tolerance: 20%; VOLTAGE: 6.3V; voltage rating: 6.3V
C7 C12-C16 C20 C22-C25 C33 C35 C39 C46 C54 = CAP_NP: CAP CER 0.22UF 6.3V 20% X5R 0402; AGILE_PN: 150-76271; CAD_APPROVED: Yes; FPLIST: CC0402_25,CC0402_HD,0402_CC; HEIGHT: 0.55MM; MFG_NAME01: MURATA; MFG_PN01: GRM155R60J224ME01; ROHS: Yes; Tolerance: 20%; VOLTAGE: 6.3V
C57 C58 = CAP_NP: CAP CER 1000PF 50V 5% C0G 0402; AGILE_PN: 150-76334; ASSY_OPT: DNP; CAD_APPROVED: Yes; FPLIST: CC0402_25,CC0402_HD,0402_CC; HEIGHT: 0.55MM; MFG_NAME01: MURATA; MFG_PN01: GRM1555C1H102JA01D; ROHS: Yes; Tolerance: 5%; VOLTAGE: 50V
C59 = CAP_NP: CAP CER 1000PF 50V 5% C0G 0402; AGILE_PN: 150-76334; CAD_APPROVED: Yes; FPLIST: CC0402_25,CC0402_HD,0402_CC; HEIGHT: 0.55MM; MFG_NAME01: MURATA; MFG_PN01: GRM1555C1H102JA01D; ROHS: Yes; Tolerance: 5%; VOLTAGE: 50V
C61 = CAP_NP: CAP CER 1.0UF 10V 10% X5R 0402; AGILE_PN: 150-75772; ASSY_OPT: DNP; CAD_APPROVED: Yes; FPLIST: CC0402_25,CC0402_HD,0402_CC; HEIGHT: 0.6MM; MFG_NAME01: YAGEO AMERICA; MFG_PN01: CC0402KRX5R6BB105; ROHS: Yes; VOLTAGE: 10V
D4 D6 D9 D10 = DIODE_SCHTKY: DIODE SCH RECT 200MA 30V AEC-Q101 SOD-523; AGILE_PN: 480-79672; CAD_APPROVED: Yes; HEIGHT: 0.65MM; MFG_NAME01: NEXPERIA; MFG_PN01: RB521S30,115; ROHS: Yes
H1-H4 = SPACER: FASTENER, STANDOFF 4.5MMX3.53XM3.0X0.5 ROUND THR .635"L BRASS; AGILE_PN: 280-76498; ASSY_OPT: DNP; CAD_APPROVED: Yes; HEIGHT: 16.13MM; MFG_NAME01: UNICORP; MFG_PN01: MSS251-R-1-A-16; ROHS: Yes
J1 = CONN_HDR_5X2: HDR 2X5 TH 100MIL CTR 338H AU 98L; AGILE_PN: 210-81467; CAD_APPROVED: Yes; HEIGHT: 8.59MM; MFG_NAME01: ANYTRONIC CORPORATION LIMITED; MFG_PN01: 0902S1005011N9T-31RF; ROHS: Yes; Temp_Range: -55DegC to +105DegC
J3-J6 J8 J35-J37 J54 = CONN_HDR_2X1: HDR 1X2 TH 100MIL SP 339H AU 98L; AGILE_PN: 210-81490; CAD_APPROVED: Yes; HEIGHT: 8.59MM; MFG_NAME01: ANYTRONIC CORPORATION LIMITED; MFG_PN01: 0901S0202011N9T-31RF; ROHS: Yes; Temp_Range: -55°C to +105°C
L2 = IND: IND PWR 1UH@100KHZ 2.6A 30% SMT; AGILE_PN: 180-77797; CAD_APPROVED: Yes; HEIGHT: 2.2MM; MFG_NAME01: Shenzhen Sunlord Electronics Co., Ltd; MFG_PN01: SWPA4020S1R0NT; PART_TYPE: INDUCTOR\POWER; ROHS: Yes; TOL: 30%; Tolerance: 30%
L6-L8 L20 = INDUCTOR_FERRITE: IND FER BEAD 120 OHM@100MHZ 0.5A 25% 0402; AGILE_PN: 180-77771; CAD_APPROVED: Yes; FPLIST: IND_0402,0402_CC; HEIGHT: 0.55MM; MFG_NAME01: Murata; MFG_PN01: BLM15AG121SN1D; PART_TYPE: FERRITE\BEAD; ROHS: Yes; Tolerance: 25%
R32 = RES: RES MF 464K 1/10W 1% AEC-Q200 0402; AGILE_PN: 470-31135; CAD_APPROVED: Yes; FPLIST: RC0402_25,RC0402_HD,0402_CC; HEIGHT: 0.40 MM; MFG_NAME01: KOA SPEER; MFG_PN01: RK73H1ETTP4643F; ROHS: Yes; Temp_Range: -55C to +155C; Tolerance: 1%
R34 = RES: RES MF 200K 1/10W 1% AEC-Q200 0402; AGILE_PN: 470-31093; CAD_APPROVED: Yes; FPLIST: RC0402_25,RC0402_HD,0402_CC; HEIGHT: 0.40 MM; MFG_NAME01: KOA SPEER; MFG_PN01: RK73H1ETTP2003F; ROHS: Yes; Temp_Range: -55C to +155C; Tolerance: 1%
R22 R35 R36 R38 R45 R47 R56 R62 R65 R68 R80 R82 R83 R85 R87 R88 R90 R94 R98 R101 R104-R107 R274 R280 R293 R312 = RES: RES MF ZERO OHM 1/16W 5% 0402; AGILE_PN: 470-75394; CAD_APPROVED: Yes; FPLIST: RC0402_25,RC0402_HD,RC0402_X2,0402_CC; HEIGHT: 0.45 MM; MFG_NAME01: ROHM; MFG_PN01: MCR01MZPJ000; ROHS: Yes; Tolerance: 5%
R21 R37 R46 R61 R63 R69 R84 R281-R283 R430 R779 R780 = RES: RES MF ZERO OHM 1/16W 5% 0402; AGILE_PN: 470-75394; ASSY_OPT: DNP; CAD_APPROVED: Yes; FPLIST: RC0402_25,RC0402_HD,RC0402_X2,0402_CC; HEIGHT: 0.45 MM; MFG_NAME01: ROHM; MFG_PN01: MCR01MZPJ000; ROHS: Yes; Tolerance: 5%
R26 R39 = RES: RES MF 100K 1/16W 5% 0402; AGILE_PN: 470-75597; ASSY_OPT: DNP; CAD_APPROVED: Yes; FPLIST: RC0402_25,RC0402_HD,0402_CC; HEIGHT: 0.40 MM; MFG_NAME01: VENKEL COMPANY; MFG_PN01: CR0402-16W-104JT; ROHS: Yes; Temp_Range: -55C to +155C; Tolerance: 5%
R40 = RES: RES MF 180K 1/10W 1% AEC-Q200 0402; AGILE_PN: 470-31088; CAD_APPROVED: Yes; FPLIST: RC0402_25,RC0402_HD,0402_CC; HEIGHT: 0.40 MM; MFG_NAME01: KOA SPEER; MFG_PN01: RK73H1ETTP1803F; ROHS: Yes; Temp_Range: -55C to +155C; Tolerance: 1%
R41 R86 R91 = RES: RES MF 10K 1/16W 5% 0402; AGILE_PN: 470-75557; CAD_APPROVED: Yes; FPLIST: RC0402_25,RC0402_HD,0402_CC; HEIGHT: 0.4 MM; MFG_NAME01: VISHAY INTERTECHNOLOGY; MFG_PN01: CRCW040210K0JNED; ROHS: Yes; Tolerance: 5%
R42 = RES: RES MF 40.2K  1/16W 1% 0402; AGILE_PN: 470-31015; CAD_APPROVED: Yes; FPLIST: RC0402_25,RC0402_HD,0402_CC; HEIGHT: 0.40 MM; MFG_NAME01: YAGEO AMERICA; MFG_PN01: RC0402FR-0740K2L; ROHS: Yes; Temp_Range: -55C to +155C; Tolerance: 1%
R50 R296 = RES: RES MF 100 OHM 1/16W 1% 0402; AGILE_PN: 470-30454; CAD_APPROVED: Yes; FPLIST: RC0402_25,RC0402_HD,0402_CC; HEIGHT: 0.4 MM; MFG_NAME01: THYE MING TECH CO LTD; MFG_PN01: CR-02FL6--100R; ROHS: Yes; Tolerance: 1%
R53 = RES: RES MF 1M 1/10W 5% AEC-Q200 0402; AGILE_PN: 470-79978; CAD_APPROVED: Yes; FPLIST: RC0402_25,RC0402_HD,0402_CC; HEIGHT: 0.4MM; MFG_NAME01: KOA SPEER; MFG_PN01: RK73B1ETTP105J; ROHS: Yes; Temp_Range: -55&#8451; to 155&#8451;; Tolerance: 5%
TP2-TP5 = TEST_POINT: TEST POINT BLK 70X220 MIL TH; AGILE_PN: 210-30155; CAD_APPROVED: Yes; HEIGHT: 5.6MM; MFG_NAME01: Keystone Electronics; ROHS: Yes
TP8 TP9 TP13 TP31-TP33 = T_POINT_R: TEST POINT PAD .035 SMT, no part to order; AGILE_PN: 510-75618; CAD_APPROVED: Yes; HEIGHT: 0.1MM; ROHS: Yes
U3 = UM1750S-00_5P: IC VREG LDO ADJ 1-5V 350mA 2.5-6V SOT23-5; AGILE_PN: 315-80554; CAD_APPROVED: Yes; HEIGHT: 1.25MM; MFG_NAME01: Union Semiconductor, Inc; ROHS: Yes
U4 = MP2144GJ_TSOT23_8P: IC SYNC STEP-DOWN SW 1.2MHZ 0.6V 2A 2.5-5.5V TSOT23-8; AGILE_PN: 315-80508; CAD_APPROVED: Yes; HEIGHT: 1MM; MFG_NAME01: MONOLITHIC POWER SYSTEMS; ROHS: Yes
U5 = UM805_4P: IC VOLT MONITOR 2.63V VTH RST 1-5.5V SOT143; AGILE_PN: 315-80564; CAD_APPROVED: Yes; HEIGHT: 1.22MM; MFG_NAME01: Union Semiconductor, Inc; ROHS: Yes
C6 C78 = CAP_NP: CAP CER 1.0UF 10V 10% X5R 0402; AGILE_PN: 150-75772; CAD_APPROVED: Yes; FPLIST: CC0402_25,CC0402_HD,0402_CC; HEIGHT: 0.6MM; MFG_NAME01: YAGEO AMERICA; MFG_PN01: CC0402KRX5R6BB105; ROHS: Yes; VOLTAGE: 10V
C18 C31 = CAP_NP: CAP CER 22UF 6.3V 20% X5R 0603; AGILE_PN: 150-78467; ASSY_OPT: DNP; CAD_APPROVED: Yes; FPLIST: CC0603_OV,CC0603,0603_CC; HEIGHT: 1MM; MFG_NAME01: Samsung; MFG_PN01: CL10A226MQ8NRNE; ROHS: Yes; Tolerance: 20%; VOLTAGE: 6.3V; voltage rating: 6.3V
C26 = CAP_NP: CAP CER 4.7UF 6.3V 20% X5R 0402; AGILE_PN: 150-78463; ASSY_OPT: DNP; CAD_APPROVED: Yes; FPLIST: CC0402_25,CC0402_HD,0402_CC; HEIGHT: 0.65MM; MFG_NAME01: TDK; MFG_PN01: C1005X5R0J475M050BC; ROHS: Yes; Tolerance: 20%; VOLTAGE: 6.3V; voltage rating: 6.3V
C36 C37 = CAP_NP: CAP CER 4.7PF 50V 0.25PF C0G 0402; AGILE_PN: 150-76335; CAD_APPROVED: Yes; FPLIST: CC0402_25,CC0402_HD,0402_CC; HEIGHT: 0.55MM; MFG_NAME01: MURATA; MFG_PN01: GRM1555C1H4R7CA01D; ROHS: Yes; Tolerance: 0.25pF; VOLTAGE: 50V
C44 C45 = CAP_NP: CAP CER 10PF 50V 5% C0G 0402; AGILE_PN: 150-75265; CAD_APPROVED: YES; FPLIST: CC0402_25,CC0402_HD,0402_CC; HEIGHT: 0.635MM; MFG_NAME01: AVX; MFG_PN01: 04025A100JAT2A; ROHS: Yes; Tolerance: 5%; VOLTAGE: 50V
D25-D27 = LED: LED GRN SGL 25MA 0603; AGILE_PN: 370-76549; CAD_APPROVED: Yes; HEIGHT: 0.85MM; MFG_NAME01: KINGBRIGHT; MFG_PN01: KPT-1608SGC; ROHS: Yes
J7 J12 J13 = CONN_HDR_2X1: HDR 1X2 TH 100MIL SP 339H AU 98L; AGILE_PN: 210-81490; ASSY_OPT: DNP; CAD_APPROVED: Yes; HEIGHT: 8.59MM; MFG_NAME01: ANYTRONIC CORPORATION LIMITED; MFG_PN01: 0901S0202011N9T-31RF; ROHS: Yes; Temp_Range: -55°C to +105°C
L1 = IND_FERRITE: IND WW FER 4.7uH@1MHz 1.4A 20% 4012; AGILE_PN: 180-78674; CAD_APPROVED: Yes; HEIGHT: 1.2MM; MFG_NAME01: TDK; MFG_PN01: VLS4012ET-4R7M; PART_TYPE: FERRITE; ROHS: Yes; Temp_Range: -40C to +105C; Tolerance: 20%
R12-R14 R16 R357 = RES: RES MF 0.02 OHM 1/10W 1% 0603; AGILE_PN: 470-80199; ASSY_OPT: DNP; CAD_APPROVED: Yes; FPLIST: RC0603_OV,RC0603,0603_CC; HEIGHT: 0.457MM; MFG_NAME01: VISHAY INTERTECHNOLOGY; MFG_PN01: WSL0603R0200FEA; ROHS: Yes; TOL: 1%; Tolerance: 1%
R17 R95-R97 R100 R102 R103 = RES: RES MF 1.0K 1/16W 5% 0402; AGILE_PN: 470-75555; CAD_APPROVED: Yes; FPLIST: RC0402_25,RC0402_HD,RC0402_X2,0402_CC; HEIGHT: 0.41mm; MFG_NAME01: VISHAY INTERTECHNOLOGY; MFG_PN01: CRCW04021K00JNED; ROHS: Yes; Tolerance: 5%
R20 = RES: RES MF 1.5K 1/16W 1% 0402; AGILE_PN: 470-80487; CAD_APPROVED: Yes; FPLIST: RC0402_25,RC0402_HD,0402_CC; HEIGHT: 0.4MM; MFG_NAME01: BOURNS; MFG_PN01: CR0402-FX-1501GLF; ROHS: Yes; Tolerance: 1%
R30 = RES: RES MF 1M 1/10W 5% AEC-Q200 0402; AGILE_PN: 470-79978; ASSY_OPT: DNP; CAD_APPROVED: Yes; FPLIST: RC0402_25,RC0402_HD,0402_CC; HEIGHT: 0.4MM; MFG_NAME01: KOA SPEER; MFG_PN01: RK73B1ETTP105J; ROHS: Yes; Temp_Range: -55&#8451; to 155&#8451;; Tolerance: 5%
R31 = RES: RES MF 2.2M 1/10W 1% AEC-Q200 0402; AGILE_PN: 470-31210; CAD_APPROVED: Yes; FPLIST: RC0402_25,RC0402_HD,0402_CC; HEIGHT: 0.40 MM; MFG_NAME01: KOA SPEER; MFG_PN01: RK73H1ETTP2204F; ROHS: Yes; Temp_Range: -55C to +155C; Tolerance: 1%
R33 = RES: RES MF 30K 1/16W 1% 0402; AGILE_PN: 470-76590; CAD_APPROVED: Yes; FPLIST: RC0402_25,RC0402_HD,0402_CC; HEIGHT: 0.4MM; MFG_NAME01: THYE MING TECH CO LTD; MFG_PN01: CR02FL6-30K; ROHS: Yes; Tolerance: 1%
R433-R435 = RES: RES MF 470 OHM 1/16W 1% 0402; AGILE_PN: 470-76469; CAD_APPROVED: Yes; FPLIST: RC0402_25,RC0402_HD,0402_CC; HEIGHT: 0.4 MM; MFG_NAME01: THYE MING TECH CO LTD; MFG_PN01: CR-02FL6--470R; ROHS: Yes; Tolerance: 1%
SW2-SW4 = SW_PB_ESW: SW SPST MOM NO PB TACT 50mA 50V SMT; AGILE_PN: 510-77562; CAD_APPROVED: Yes; HEIGHT: 5MM; MFG_NAME01: E SWITCH; MFG_PN01: TL3301AF260QG/TR; ROHS: Yes
U2 = SGM803_SOT23-3P: IC VOLT MONITOR 2.63V RST VTH 1-5.5V AUTO SOT-23; AGILE_PN: 315-80553; CAD_APPROVED: Yes; HEIGHT: 1.25MM; MFG_NAME01: Union Semiconductor, Inc; ROHS: Yes
Y2 = CRYSTAL: XTAL 32.768KHZ 7PF 20PPM -- SMT; AGILE_PN: 230-78102; CAD_APPROVED: Yes; HEIGHT: 0.9MM; MFG_NAME01: EPSON ELECTRONICS; MFG_PN01: FC-135 32.7680KA-AG3; ROHS: Yes
Y4 = XTAL_13: XTAL 24MHZ -- 20PPM 2.0X1.6MM SMD; AGILE_PN: 230-78216; CAD_APPROVED: Yes; HEIGHT: 0.7MM; MFG_NAME01: MURATA; MFG_PN01: XRCGB24M000F2P29R0; ROHS: Yes; Temp_Range: -30C to 85C
R295 R303 R429 = RES: RES MF 10K 1/16W 5% 0402; AGILE_PN: 470-75557; CAD_APPROVED: Yes; FPLIST: RC0402_25,RC0402_HD,0402_CC; HEIGHT: 0.4 MM; MFG_NAME01: VISHAY INTERTECHNOLOGY; MFG_PN01: CRCW040210K0JNED; ROHS: Yes; TOL: 5%; Tolerance: 5%
U1 = MIMXRT1015DAF5A: IC CPU ARM Cortex-M7 500MHZ 1.3V LQFP100; AGILE_PN: TMP-WF-34226; CAD_APPROVED: Yes; HEIGHT: 1.7 MM; MFG_NAME01: NXP SEMICONDUCTORS; PRE_APN: 330-77091; ROHS: Yes; Temp_Range: 0°C ~ 95°C
C81 C84 = CAP_NP: CAP CER 4.7UF 6.3V 20% X5R 0402; AGILE_PN: 150-78463; CAD_APPROVED: Yes; FPLIST: CC0402_25,CC0402_HD,0402_CC; HEIGHT: 0.65MM; MFG_NAME01: TDK; MFG_PN01: C1005X5R0J475M050BC; ROHS: Yes; TOL: 20%; Tolerance: 20%; VOLTAGE: 6.3V
J9 = USB_MINI_AB_RECEPTACLE: CON 5 USB MICRO_AB RA SKT SMT 0.65MM SP 110H AU; AGILE_PN: 211-80104; CAD_APPROVED: Yes; HEIGHT: 2.8MM; MFG_NAME01: ANYTRONIC CORPORATION LIMITED; MFG_PN01: 23971101#LCP-58RF; ROHS: Yes; Temp_Range: -55&#8451; to 105&#8451;
L3 L5 = BEAD: IND FER BEAD 330OHM@100MHZ 1.7A 0603; AGILE_PN: 180-78156; CAD_APPROVED: Yes; HEIGHT: 0.95MM; MFG_NAME01: TDK; MFG_PN01: MPZ1608S331A; PART_TYPE: FERRITE\BEAD; ROHS: Yes; TOL: 25%; Tolerance: 25%
L4 = DLW43: IND CHK 90 OHM@100MHZ 330MA 25% 0805; AGILE_PN: 180-76336; CAD_APPROVED: Yes; HEIGHT: 1MM; MFG_NAME01: MURATA; MFG_PN01: DLW21HN900SQ2L; PART_TYPE: CHOKE; ROHS: Yes; Tolerance: 25%
Q9 = 2SK3018: TRANS MOSFET N-CH 30V .1A SOT-323; AGILE_PN: 480-75317; CAD_APPROVED: Yes; HEIGHT: 0.9MM; MFG_NAME01: ROHM; MFG_PN01: 2SK3018T106; ROHS: Yes
R64 R66 R781 = RES: RES MF 100K 1/16W 5% 0402; AGILE_PN: 470-75597; CAD_APPROVED: Yes; FPLIST: RC0402_25,RC0402_HD,0402_CC; HEIGHT: 0.40 MM; MFG_NAME01: VENKEL COMPANY; MFG_PN01: CR0402-16W-104JT; ROHS: Yes; TOL: 5%; Temp_Range: -55C to +155C; Tolerance: 5%
R67 = RES: RES MF 100K 1/16W 1% 0402; AGILE_PN: 470-76240; CAD_APPROVED: Yes; FPLIST: RC0402_25,RC0402_HD,0402_CC; HEIGHT: 0.4MM; MFG_NAME01: NIC COMPONENTS CORP; MFG_PN01: NRCL04F1003TRF; ROHS: Yes; Tolerance: 1%
R70 = RES: RES MF 10K 1/16W 5% 0402; AGILE_PN: 470-75557; ASSY_OPT: DNP; CAD_APPROVED: Yes; FPLIST: RC0402_25,RC0402_HD,0402_CC; HEIGHT: 0.4 MM; MFG_NAME01: VISHAY INTERTECHNOLOGY; MFG_PN01: CRCW040210K0JNED; ROHS: Yes; Tolerance: 5%
U7 = NX5P3090UK_WLCSP12: IC USB PD TYPE C CURRENT LIMITED PWR SW 2.5-5.5V WLCSP12; AGILE_PN: 312-81574; CAD_APPROVED: Yes; HEIGHT: 0.565 MM; MFG_NAME01: NXP SEMICONDUCTORS; MFG_PN01: NX5P3090UK,012; ROHS: Yes
U8 = RCLAMP1654P_NEW: DIODE TVS ARRAY 3 5.5V SLP1616P6; AGILE_PN: 480-78843; CAD_APPROVED: Yes; HEIGHT: 0.65MM; MFG_NAME01: SEMTECH CORP; ROHS: Yes
C101 C104 = CAP_NP: CAP CER 220PF 50V 5% C0G 0402; AGILE_PN: 150-30297; CAD_APPROVED: Yes; FPLIST: CC0402_25,CC0402_HD,0402_CC; HEIGHT: 0.55MM; MFG_NAME01: KEMET; MFG_PN01: C0402C221J5GAC; ROHS: Yes; Tolerance: 5%; VOLTAGE: 50V
C102 C103 = CAP_NP: CAP CER 22UF 6.3V 20% X5R 0603; AGILE_PN: 150-78467; CAD_APPROVED: Yes; FPLIST: CC0603_OV,CC0603,0603_CC; HEIGHT: 1MM; MFG_NAME01: Samsung; MFG_PN01: CL10A226MQ8NRNE; ROHS: Yes; Tolerance: 20%; VOLTAGE: 6.3V
C107 C110 C116-C119 = CAP_NP: CAP CER 15PF 16V 5% C0G 0402; AGILE_PN: 150-75720; CAD_APPROVED: Yes; FPLIST: CC0402_25,CC0402_HD,0402_CC; HEIGHT: 0.55MM; MFG_NAME01: KEMET; MFG_PN01: C0402C150J4GAC; ROHS: Yes; Tolerance: 5%; VOLTAGE: 16V
C120-C125 = CAP_NP: CAP CER 15PF 16V 5% C0G 0402; AGILE_PN: 150-75720; ASSY_OPT: DNP; CAD_APPROVED: Yes; FPLIST: CC0402_25,CC0402_HD,0402_CC; HEIGHT: 0.55MM; MFG_NAME01: KEMET; MFG_PN01: C0402C150J4GAC; ROHS: Yes; Tolerance: 5%; VOLTAGE: 16V
J11 = CONN_AUDIOJACK_6P: CON 6 AUD JACK RA SMT -- 191H AU; AGILE_PN: 211-79704; CAD_APPROVED: Yes; HEIGHT: 4.85 MM; MFG_NAME01: SHENZHEN ATOM TECHNOLOGY CO.,LTD; ROHS: Yes
P1 = MIC_POM: AUDIO DEVICE MIC 0.5MA 2V 38-48+/-3dB 2.2KOHM 6MM TH; AGILE_PN: 510-77987; CAD_APPROVED: Yes; HEIGHT: 2.4MM; MFG_NAME01: Soberton Inc; ROHS: Yes
R81 = RES: RES MF 100K 1/16W 5% 0402; AGILE_PN: 470-75597; CAD_APPROVED: Yes; FPLIST: RC0402_25,RC0402_HD,0402_CC; HEIGHT: 0.40 MM; MFG_NAME01: VENKEL COMPANY; MFG_PN01: CR0402-16W-104JT; ROHS: Yes; Temp_Range: -55C to +155C; Tolerance: 5%
R92 R93 = RES: RES MF 4.7K 1/16W 5% 0402; AGILE_PN: 470-75626; CAD_APPROVED: Yes; FPLIST: RC0402_25,RC0402_HD,0402_CC; HEIGHT: 0.41mm; MFG_NAME01: NIC COMPONENTS CORP; MFG_PN01: NRCL04J472TRF; ROHS: Yes; Tolerance: 5%
R99 = RES: RES MF 10K 1/16W 5% 0402; AGILE_PN: 470-75557; ASSY_OPT: DNP; CAD_APPROVED: Yes; FPLIST: RC0402_25,RC0402_HD,0402_CC; HEIGHT: 0.4 MM; MFG_NAME01: VISHAY INTERTECHNOLOGY; MFG_PN01: CRCW040210K0JNED; ROHS: Yes; TOL: 5%; Tolerance: 5%
TVS2-TVS5 = DIODE_TVS_BIDIR: DIODE SUPPRESSOR 16A@30NS 5V@1UA SOD-523; AGILE_PN: 480-76937; CAD_APPROVED: Yes; HEIGHT: 0.7MM; MFG_NAME01: on semiconductor; ROHS: Yes
U10 = WM8960_QFN_33P: IC CODEC STEREO WITH CLASS D SPEAKER DRIVER 1.71-3.6V QFN32; AGILE_PN: 315-79450; CAD_APPROVED: Yes; HEIGHT: 1MM; MFG_NAME01: WOLFSON MICROELECTRONICS; MFG_PN01: WM8960CGEFL/RV; ROHS: Yes
C191 = CAP_NP: CAP CER 0.01UF 16V 20% X7R 0402; AGILE_PN: 150-30082; CAD_APPROVED: Yes; FPLIST: CC0402_25,CC0402_HD,0402_CC; HEIGHT: 0.56MM; MFG_NAME01: AVX; MFG_PN01: 0402YC103MAT2A; ROHS: Yes; TOL: 20%; Tolerance: 20%; VOLTAGE: 16V
J52 J53 = KLPX0848A: CON 2 RCA SKT RA TH BLACK -- 512H SN; AGILE_PN: 210-78092; ASSY_OPT: DNP; CAD_APPROVED: Yes; HEIGHT: 13MM; MFG_NAME01: KYCON; MFG_PN01: KLPX-0848A-2-B; PRIORITY_PN: 009-00703; ROHS: Yes
R273 = RES: RES MF 374 OHM 1/8W 1% 0805; AGILE_PN: 470-80029; CAD_APPROVED: Yes; FPLIST: RC0805_OV,RC0805,0805_CC; HEIGHT: 0.5MM; MFG_NAME01: VISHAY INTERTECHNOLOGY; MFG_PN01: CRCW0805374RFKEA; ROHS: Yes; TOL: 1%; Tolerance: 1%
R298 = RES: RES TF 75.0 OHM 1/8W 1% 0805; AGILE_PN: 470-76238; CAD_APPROVED: Yes; FPLIST: RC0805_OV,RC0805,0805_CC; HEIGHT: 0.6 MM; MFG_NAME01: YAGEO AMERICA; MFG_PN01: RC0805FR-0775RL; ROHS: Yes; TOL: 1%; Tolerance: 1%
R431 = RES: RES MF 93.1 OHM 1/8W 1% AEC-Q200 0603; AGILE_PN: 470-77900; CAD_APPROVED: Yes; FPLIST: RC0603_OV,RC0603,0603_CC; HEIGHT: 0.55MM; MFG_NAME01: KOA SPEER; MFG_PN01: RK73H1JTTD93R1F; ROHS: Yes; TOL: 1%; Temp_Range: -55C to +155C; Tolerance: 1%
T1 T2 = XFMR: XFMR SMT 780UH/780UH/250MA WIDEBAND XFMR6_6.6X6.2; AGILE_PN: 560-75273; ASSY_OPT: DNP; CAD_APPROVED: Yes; HEIGHT: 4.82MM; MFG_NAME01: COILCRAFT; MFG_PN01: TTWB1010LD; PART_TYPE: TRANSFORMERS; PRIORITY_PN: 051-TTWB1010LD; ROHS: Yes; ROOM: SPDIF
U37 = 100201_SO-1: IC BUF TS 1.65-5.5V SOT-353; AGILE_PN: 312-30127; CAD_APPROVED: YES; HEIGHT: 1.1 MM; MFG_NAME01: ON SEMICONDUCTOR; MFG_PN01: NL17SZ126DFT2G; PRIORITY_PN: 051-NL17SZ126DF; ROHS: Yes
U43 = 74AUP2G06GW: IC INVERTER ULP-A DUAL 0.93.6V MICROPAK6; AGILE_PN: 315-81072; CAD_APPROVED: Yes; HEIGHT: 0.55MM; MFG_NAME01: FAIRCHILD; ROHS: Yes

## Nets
5V_EXT_S: J1.5(A3) J1.7(A4)
5V_SYS: C40.1 C41.1 C179.1 C180.1 L20.2 R38.1 R62.1 R82.1 U3.1(IN) U3.3(~{SHDN}) ; also on sheet 13
5V_USB_OTG: C78.1 C81.1 C84.1 L3.2 R312.1 U1.38(USB_OTG1_VBUS) U7.C2(VBUS1) U7.D1(VBUS2) U7.D2(VBUS3)
5V_USB_OTG_S: J1.3(A2) R312.2
GND: C6.2 C7.2 C12.2 C13.2 C14.2 C15.2 C16.2 C17.2 C18.2 C19.2 C20.2 C21.2 C22.2 C23.2 C24.2 C25.2 C26.2 C28.2 C29.2 C31.2 C32.2 C33.2 C35.2 C36.2 C37.2 C38.2 C39.2 C40.2 C41.2 C42.2 C43.2 C44.2 C45.2 C46.2 C47.2 C48.2 C49.2 C50.2 C51.2 C52.2 C53.2 C54.2 C55.2 C56.2 C57.2 C58.2 C59.2 C60.2 C66.2 C67.2 C68.2 C69.2 C70.2 C71.2 C72.2 C73.2 C78.2 C79.2 C80.2 C81.2 C82.2 C83.2 C84.2 C91.2 C92.2 C93.2 C94.2 C95.2 C96.2 C97.2 C98.2 C99.2 C100.2 C101.1 C104.2 C105.2 C106.2 C107.1 C108.2 C109.2 C110.1 C116.2 C117.2 C118.2 C119.2 C120.1 C121.1 C124.2 C125.2 C157.2 C172.2 C173.2 C174.2 C176.2 C179.2 C180.2 C195.2 H1.1(NC) H2.1(NC) H3.1(NC) H4.1(NC) J1.9(A5) J1.10(B5) J7.1 J9.5(P5) J11.1 L5.2 Q9.1(SOURCE) R31.2 R34.2 R42.2 R53.2 R67.2 R70.2 R86.1 R91.2 R103.1 R274.2 R298.2 R303.2 R429.2 SW2.1(A1) SW2.2(A2) SW3.1(A1) SW3.2(A2) SW4.1(A1) SW4.2(A2) T1.4 TP2.1 TP3.1 TP4.1 TP5.1 TVS2.1(A1) TVS3.1(A1) TVS4.1(A1) TVS5.1(A1) U1.19(VSS1) U1.24(DCDC_GND) U1.29(VSS2) U1.32(TEST_MODE) U1.39(VSS3) U1.43(NGND_KEL0) U1.49(VSS4) U1.59(VSS5) U1.70(VSS6) U1.79(VSS7) U1.92(VSS8) U2.1(GND) U3.2(GND) U4.4(PGND) U4.6(AGND) U5.1(GND) U7.B3(GND1) U7.C3(GND2) U7.D3(GND3) U8.7(GND) U10.9(DGND) U10.20(SPKGND2) U10.24(SPKGND1) U10.28(AGND) U10.33(GND_PADDLE) U37.3(GND) U43.2(GND) Y4.2 Y4.4 ; also on sheet 9 10 11 12 13
P5V_SDA_S: J1.1(A1) ; also on sheet 10
VDD_COIN_3V: D6.A J7.2 R17.1
VDD_HIGH_IN_3V3: C56.1 J5.1 R14.1 R45.2
VDD_HIGH_IN_MCU: C19.1 C20.1 J5.2 R14.2 U1.48(VDD_HIGH_IN)
VDD_SNVS_3V3: C48.1 C60.1 D4.A R36.2 R37.2 U5.4(VCC)
VDD_SNVS_IN: C23.1 J6.2 R16.2 R26.1 U1.34(VDD_SNVS_IN)
VDD_SOC_IN: C12.1 C13.1 C14.1 C15.1 C16.1 C17.1 C18.1 J4.1 R13.1 U1.18(VDD_SOC_IN_1) U1.28(VDD_SOC_IN_2) U1.69(VDD_SOC_IN_3) U1.81(VDD_SOC_IN_4) U1.91(VDD_SOC_IN_5)
VDD_USB_3V: C79.1 C80.1 U1.40(VDD_USB_CAP)
VDDA_ADC_3P3_MCU: C6.1 C7.1 J3.2 R12.2 U1.51(VDDA_ADC_3P3)
VDDA_ADC_3V3: C47.1 J3.1 R12.1 R35.2
ADC12_1: U1.61(GPIO_AD_B0_14) ; also on sheet 12 13
ADC12_2: U1.60(GPIO_AD_B0_15) ; also on sheet 12 13
ARM_TRACE_SWO: R293.1 U1.74(GPIO_AD_B0_04) ; also on sheet 10 13
AUD_INT: R83.1 R84.1 U1.2(GPIO_EMC_08)
DCDC_3V3: J8.1 J35.2 R20.1 R35.1 R37.1 R45.1 R47.1 R56.1 R64.1 R66.1 R80.1 R433.1 R434.1 R435.1 R781.1 ; also on sheet 9 10 11 12 13
DCDC_3V3_PG: C57.1 C58.1 TP9.1(TP) U4.1(PG)
DCDC_OUT: C38.1 C39.1 J4.2 L1.1 R13.2
FlexSPI_CLK_A: U1.12(GPIO_SD_B1_07) ; also on sheet 9
FlexSPI_D0_A: U1.11(GPIO_SD_B1_08) ; also on sheet 9
FlexSPI_D1_A: U1.9(GPIO_SD_B1_10) ; also on sheet 9
FlexSPI_D2_A: U1.10(GPIO_SD_B1_09) ; also on sheet 9
FlexSPI_D3_A: U1.13(GPIO_SD_B1_06) ; also on sheet 9
FlexSPI_SS0: U1.8(GPIO_SD_B1_11) ; also on sheet 9
GPIO SD_B1_00: D25.C(CATHODE) U1.22(GPIO_SD_B1_00)
GPIO SD_B1_01: D26.C(CATHODE) U1.21(GPIO_SD_B1_01)
GPIO SD_B1_02: D27.C(CATHODE) U1.17(GPIO_SD_B1_02)
GPIO_AD_B0_05: U1.73(GPIO_AD_B0_05) ; also on sheet 13
GPIO_AD_B0_10: U1.65(GPIO_AD_B0_10) ; also on sheet 12 13
GPIO_AD_B0_11: R293.2 U1.64(GPIO_AD_B0_11) ; also on sheet 12 13
GPIO_AD_B0_12: U1.63(GPIO_AD_B0_12) ; also on sheet 12 13
GPIO_AD_B0_13: U1.62(GPIO_AD_B0_13) ; also on sheet 12 13
GPIO_AD_B1_10: R69.1 U1.57(GPIO_AD_B1_10) ; also on sheet 13
GPIO_AD_B1_11: Q9.2(GATE) R68.2 R781.2 U1.56(GPIO_AD_B1_11) ; also on sheet 13
GPIO_AD_B1_12: R65.1 U1.55(GPIO_AD_B1_12) ; also on sheet 13
GPIO_AD_B1_13: U1.54(GPIO_AD_B1_13) ; also on sheet 13
GPIO_AD_B1_14: R92.2 U1.53(GPIO_AD_B1_14) U10.17(SCLK) ; also on sheet 12 13
GPIO_AD_B1_15: R93.2 U1.52(GPIO_AD_B1_15) U10.18(SDIN) ; also on sheet 12 13
GPIO_EMC_16: U1.100(GPIO_EMC_16) ; also on sheet 11
GPIO_EMC_17: U1.99(GPIO_EMC_17) ; also on sheet 11
GPIO_EMC_18: R779.1 U1.98(GPIO_EMC_18) ; also on sheet 11
GPIO_EMC_19: R780.1 U1.97(GPIO_EMC_19) ; also on sheet 11
GPIO_EMC_20: R90.1 U1.96(GPIO_EMC_20) ; also on sheet 11 13
GPIO_EMC_21: R88.1 U1.94(GPIO_EMC_21) ; also on sheet 11 13
GPIO_EMC_22: R283.1 U1.93(GPIO_EMC_22) ; also on sheet 11 13
GPIO_EMC_23: R282.1 U1.90(GPIO_EMC_23) ; also on sheet 11
GPIO_EMC_24: R281.1 U1.89(GPIO_EMC_24) ; also on sheet 11 13
GPIO_EMC_25: R280.1 U1.88(GPIO_EMC_25) ; also on sheet 11 13
GPIO_EMC_26: R87.1 R780.2 U1.87(GPIO_EMC_26) ; also on sheet 11 13
GPIO_EMC_27: R85.1 R779.2 U1.86(GPIO_EMC_27) ; also on sheet 11 13
GPIO_EMC_32: U1.85(GPIO_EMC_32) ; also on sheet 12 13
GPIO_EMC_33: U1.84(GPIO_EMC_33) ; also on sheet 12 13
GPIO_EMC_34: U1.83(GPIO_EMC_34) ; also on sheet 13
GPIO_EMC_35: U1.82(GPIO_EMC_35) ; also on sheet 13
HP_JD: J11.5 R81.2 R84.2 TVS3.2(A2) U10.7(RINPUT3/JD3)
HP_L: C102.1 U10.31(HP_L)
HP_MIC1N: C110.2 C112.1 U10.4(LINPUT1)
HP_MIC1P: C115.1 C116.1 U10.2(LINPUT3/JD2)
HP_R: C103.1 U10.29(HP_R)
INT1_COMBO: U1.67(GPIO_AD_B0_08) ; also on sheet 12
INT2_COMBO: U1.66(GPIO_AD_B0_09) ; also on sheet 12
JTAG_TCK: U1.77(GPIO_AD_B0_01) ; also on sheet 10 13
JTAG_TDI: C61.1 U1.75(GPIO_AD_B0_03) ; also on sheet 10 13
JTAG_TMS: U1.78(GPIO_AD_B0_00) ; also on sheet 10 13
LPUART1_RXD: U1.68(GPIO_AD_B0_07) ; also on sheet 10
LPUART1_TXD: U1.72(GPIO_AD_B0_06) ; also on sheet 10
LPUART3_RX: U1.3(GPIO_EMC_07) ; also on sheet 12
LPUART3_TX: U1.4(GPIO_EMC_06) ; also on sheet 12
MAIN_MIC2N: C114.2 C119.1 U10.5(RINPUT1)
MAIN_MIC2P: C107.2 C111.2 U10.6(RINPUT2)
MCU_DCDC_IN: C31.1 C32.1 C33.1 C35.1 J37.1 R33.1 R357.1 U1.23(DCDC_IN) U1.27(DCDC_IN_Q)
MCU_DCDC_IN_3V3: C55.1 J37.2 R47.2 R357.2
MICBIAS: C98.1 R94.1 R95.1 U10.1(MICBIAS)
NVCC_GPIO_3V3: C66.1 C67.1 C68.1 C69.1 C70.1 C71.1 C72.1 C73.1 C176.1 R56.2 U1.5(NVCC_GPIO_1) U1.20(NVCC_GPIO_2) U1.58(NVCC_GPIO_3) U1.71(NVCC_GPIO_4) U1.80(NVCC_GPIO_5) U1.95(NVCC_GPIO_6)
ONOFF: C172.1 SW2.3(B1) SW2.4(B2) U1.30(ONOFF)
OTG1_DN: L4.1 R61.2 U1.41(USB_OTG1_DN)
OTG1_DP: L4.4 R63.2 U1.42(USB_OTG1_DP)
PMIC_ON_REQ: R41.2 U1.33(PMIC_ON_REQ)
POR_B: C28.1 R22.2 R26.2 U1.31(POR_B) ; also on sheet 10 13
POR_BUTTON: C173.1 R50.1 SW3.3(B1) SW3.4(B2)
SPDIF_BUF: R273.1 R430.2 U37.4(Y)
SPDIF_COAX_OUT: J53.2 T2.1
SPDIF_GND_PRI: R274.1 R431.2 T2.4
SPDIF_IN: J36.1 U1.6(GPIO_EMC_05)
SPDIF_OUT: J54.2 U1.7(GPIO_EMC_04)
SPDIF_OUT_PRI: C171.2 R431.1 T2.6
SPDIF_VCC: C157.1 C195.1 J35.1 U37.1(OE) U37.5(VCC) U43.5(VCC)
SPK_LN: R105.1 U10.23(SPK_LN)
SPK_LP: R107.1 U10.25(SPK_LP)
SPK_RN: R104.1 U10.19(SPK_RN)
SPK_RP: R106.1 U10.22(SPK_RP)
USER_BUTTON: C174.1 SW4.3(B1) SW4.4(B2) U1.1(GPIO_EMC_09)
VAUD_3V3: C91.1 C92.1 C93.1 C94.1 R80.2 R81.1 R92.1 R93.1 U10.8(DCVDD) U10.10(DBVDD) U10.32(AVDD)
VLDO_3V3: C42.1 C43.1 R32.1 R36.1 U3.5(OUT)
N99825452: C95.1 C96.1 C97.1 C99.1 R82.2 U10.21(SPKVDD2) U10.26(SPKVDD1)
N99827287: C100.1 U10.27(VMID)
N99827729: R83.2 U10.15(ADCLRC/GPIO1)
N99827749: R85.2 U10.13(DACLRC)
N99827769: R87.2 U10.12(BCLK)
N99827789: R88.2 U10.16(ADCDAT)
N99827809: R280.2 R281.2 R282.2 R283.2 U10.14(DACDAT)
N99827829: R90.2 U10.11(MCLK)
N99827958: C120.2 C122.1 J12.2 R104.2
N99827962: C122.2 C124.1 J12.1 R106.2
N99828318: C121.2 C123.1 J13.2 R105.2
N99828322: C123.2 C125.1 J13.1 R107.2
N99833003: J9.S1(SHLD1) J9.S2(SHLD2) J9.S3(SHLD3) J9.S4(SHLD4) L5.1
N99833017: J9.1(P1) L3.1 U8.6(VBUS)
N99833020: J9.4(P4) R68.1 U8.3(USB_ID)
N99833038: J9.2(P2) L4.2 R61.1 U8.1(DM)
N99833040: J9.3(P3) L4.3 R63.1 U8.2(DP)
N99903207: C102.2 L6.1 R86.2
N99903209: C103.2 L7.1 R91.1
N99903219: C104.1 J11.3 L7.2 TVS4.2(A2)
N99903223: C101.2 J11.2 L6.2 TVS2.2(A2)
N99903738: J11.4 L8.2 TVS5.2(A2)
N99904959: C112.2 R97.2 R100.1
N99904961: C115.2 C117.1 C118.1 L8.1 R100.2
N99904975: C108.1 C109.1 R94.2 R97.1
N99907436: C113.2 R102.2 R103.2
N99907447: C114.1 R99.2 R101.2 R102.1
N99907449: C111.1 R96.2 R98.2 R99.1
N99907458: C105.1 C106.1 C113.1 R95.2 R96.1
N99907542: P1.1(Out) R98.1
N99907546: P1.2(GND) R101.1
N100054652: J1.2(B1) J1.4(B2) J1.6(B3) J1.8(B4) L20.1
N101139052: C82.1 C83.1 R62.2 U7.B1(VINT1) U7.B2(VINT2) U7.C1(VINT3)
N101140611: Q9.3(DRAIN) R66.2 R69.2 R70.1 U7.A1(EN)
N101140956: R64.2 R65.2 U7.A2(~{FAULT})
N101141371: R67.1 U7.A3(ILIM)
N101702341: C61.2 D10.C R53.1
N101702353: D9.A D10.A R46.1 U5.3(~{MR})
N101702355: C52.1 C53.1 J8.2 L2.2 R40.1 TP8.1(TP) U4.5(OUT)
N101702359: C54.1 R39.2 R41.1 R46.2 U4.8(EN) U5.2(~{RESET})
N101702363: C59.1 D9.C R50.2
N101702375: C49.1 C50.1 C51.1 R38.2 R39.1 U4.2(VIN)
N101702405: R40.2 R42.1 U4.7(FB)
N101702421: L2.1 U4.3(SW)
N101703684: R32.2 R34.1 U3.4(FB)
N101728688: C21.1 C22.1 U1.44(VDD_HIGH_CAP)
N101728690: C25.1 C26.1 U1.50(NVCC_PLL)
N101728753: C24.1 U1.35(VDD_SNVS_CAP)
N101728854: C29.1 R20.2 R21.1 U2.3(VCC)
N101728887: R21.2 R22.1 U2.2(~{RESET})
N101728999: C37.1 R30.2 U1.47(XTALO) Y4.1
N101729003: C36.1 R30.1 R31.1 U1.46(XTALI) Y4.3
N101729136: C44.1 U1.36(RTC_XTALI) Y2.1
N101729151: C45.1 U1.37(RTC_XTALO) Y2.2
N101729335: L1.2 U1.25(DCDC_LP)
N101729382: C46.1 R33.2 U1.26(DCDC_PSWITCH)
N101729433: D4.C D6.C J6.1 R16.1 R17.2
N101730981: TP13.1(TP) U1.45(USB_OTG1_CHD_B)
N101741256: R303.1 U1.76(GPIO_AD_B0_02)
N101741994: TP31.1(TP) U1.16(GPIO_SD_B1_03)
N101742024: TP32.1(TP) U1.15(GPIO_SD_B1_04)
N101742043: TP33.1(TP) U1.14(GPIO_SD_B1_05)
N101757254: C199.1 J52.2
N101757256: J52.1 T1.3
N101757272: R295.1 R296.2 U43.1(1A)
N101757274: C171.1 R273.2
N101757283: C199.2 T1.1
N101757285: C191.1 R298.1 T1.6
N101757291: C191.2 R296.1
N101757293: R295.2 R429.1 U43.3(2A) U43.6(1Y)
N101757305: J36.2 U43.4(2Y)
N101757324: J54.1 R430.1 U37.2(A)
N101757364: J53.1 T2.3
N101761326: D25.A(ANODE) R433.2
N101761351: D26.A(ANODE) R434.2
N101761384: D27.A(ANODE) R435.2

Not connected (* = marked no-connect by the designer): J11 6*; U8 4(NC1)* 5(NC2)*; U10 3(LINPUT2)* 30(OUT3)*

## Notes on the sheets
sheet 1
- SPDIF Interface
- Default:Open
- SPDIF COAX INPUT
- SPDIF COAX OUTPUT
sheet 2
- MIMXRT1015-EVK
- Table of Content
- Revision History
- Page 1
- COVER
- Rev. Code
- Date
- By
- Description
- Page 2
- BLOCK DIAGRAM
- A
- 2018-10-30
- Shawn Shi
- A Version for pilot board production
- Page 3
- MAIN POWER
- B
- 2018-11-30
- Shawn Shi
- Correct net issue for SDRAM_3V3 and VDD_3V3
- Page 4
- MIMXRT1015DAF5A PART1
- Page 5
- MIMXRT1015DAF5A PART2
- Page 6
- USB
- Page 7
- SAI
- Page 8
- SPDIF
- Page 9
- FLEXSPI FLASH
- Page 10
- ARDUINO/JTAG
- Page 11
- FREELINK
- Page 12
- BOOT
- MISC
- Page 13
- Page 14
- Page 15
- Page 16
- Page 17
- Page 18
- Page 19
- Page 20
- Page 21
- Page 22
- Page 23
- Page 24
- Page 25
- Page 26
- Page 26
- Page 27
- Page 28
- 3. Device type number is for reference only. The number
  varies with the manufacturer.
- 1. Unless Otherwise Specified:
- All resistors are in ohms, 1/16 Watt,0402
- 4. Special signal usage:
- All capacitors are in uF,0402
- _B Denotes - Active-Low Signal
- All voltages are DC
- <> or [] Denotes - Vectored Signals
- All polarized capacitors are aluminum electrolytic
- 5. Interpret diagram in accordance with American
  National Standards Institute specifications, current
  revision, with the exception of logic block symbology.
- 2. Interrupted lines coded with the same letter or letter
      combinations are electrically connected.
sheet 3
- # MIMXRT1015-EVK
- #####  Blcok Diagram Rev B#####
- JTAG/OPENSDA
- BUTTON/LED
- Motion Sensors
- PIN Header
- HMI
- Combo FXOS8700CQ
- JTAG/OPENSDA
- GPIOs
- I2C/INT
- QSPI Flash
- USB/5V
- FlexSPI
- POWER
- POWER
- FlexSPI
- Adesto AT25SF128A-SHB-T
- NXP
    IMXRT1015
- USB OTG
- USB OTG1
- LPSPI
- LPSPI Flash
- USB
- LPSPI
- Macronix AT45DB041E
- I2S
- SPDIF
- Arduino
- CODEC
- ARDUINO
- SPDIF
- Wolfson WM8960
- Function RESERVED
- PIN Header
- HP
- MIC
sheet 4
- Main Power
- USB POWER SUPPLY
- VDDHIGH / NVCC_xxx
- Current 2A
  I_Quiescent : 40μA
- 5V
- Default: 1-2
- 5V_EXT_S is for external supply
- Vfb=0.6V
- # R26/R30 = 4.5
- 3V3 LDO for SNVS
- # PG pin is pulled up to
  VIN by the internal
  resistor 500K OHM
- Vfb=1V
- # GPIO/WDOG PWR OFF->ON
- SNVS
- ADC
- DCDC_IN
- VDD_HIGH_IN
- Ground TPs
- Board Mounting Holes
- Layout Note: Place Ground TPs
  to assist signal measurement.
sheet 5
- Default: 1-2
- Up to 34.5mA
- Default: 1-2
- Up to 75mA
- VDDA_2P5_CAP
- VDDA_1P1_CAP
- Default: 1-2
- Up to 1mA
- Default: 1-2
- BATTERY SUPPLY
- # Open
  Drain
- FOR OSC STARTUP
- PSWITCH RC Delay
- BUTTON
- USER LEDS
- # CPU ONOFF Button
- # System Reset Button
- LED1
- LED2
- LED3
- # System Reset Button
sheet 6
- MCU PINOUT
- Up to 25 mA
- CCM_CLKO2
- EWM_OUT_B
- DQS Reserved
- CLOSE TO PAD
sheet 7
- USB POWER
- USB OTG
- MAX 500 mA @5V
- 0ohm and inductor share same package
sheet 8
- OFF, SLEEP MODE
- MAX 50 mA @3.3V
- DCVDD
  DBVDD
  AVDD
  SPKVDD
- 1.71V - 3.6V
  1.71V - 3.6V
  2.70V - 3.6V
  2.70V - 5.5V
- HP JACK
- MAX 0.5A @5V
- # HP_DET:
      LOW : REMOVE
      HIGH : PLUG
- #define WM8960_I2C_ADDR 0x1A
- Main Board MIC
- HP MIC
- Speaker
